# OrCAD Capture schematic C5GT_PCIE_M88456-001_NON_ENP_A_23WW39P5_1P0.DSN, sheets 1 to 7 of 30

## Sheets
1 Title, Note, Block Diagram: title: Cyclone V_GT FPGA DK (Non-ENP); note: M88456-001 (100-0330705-A1)
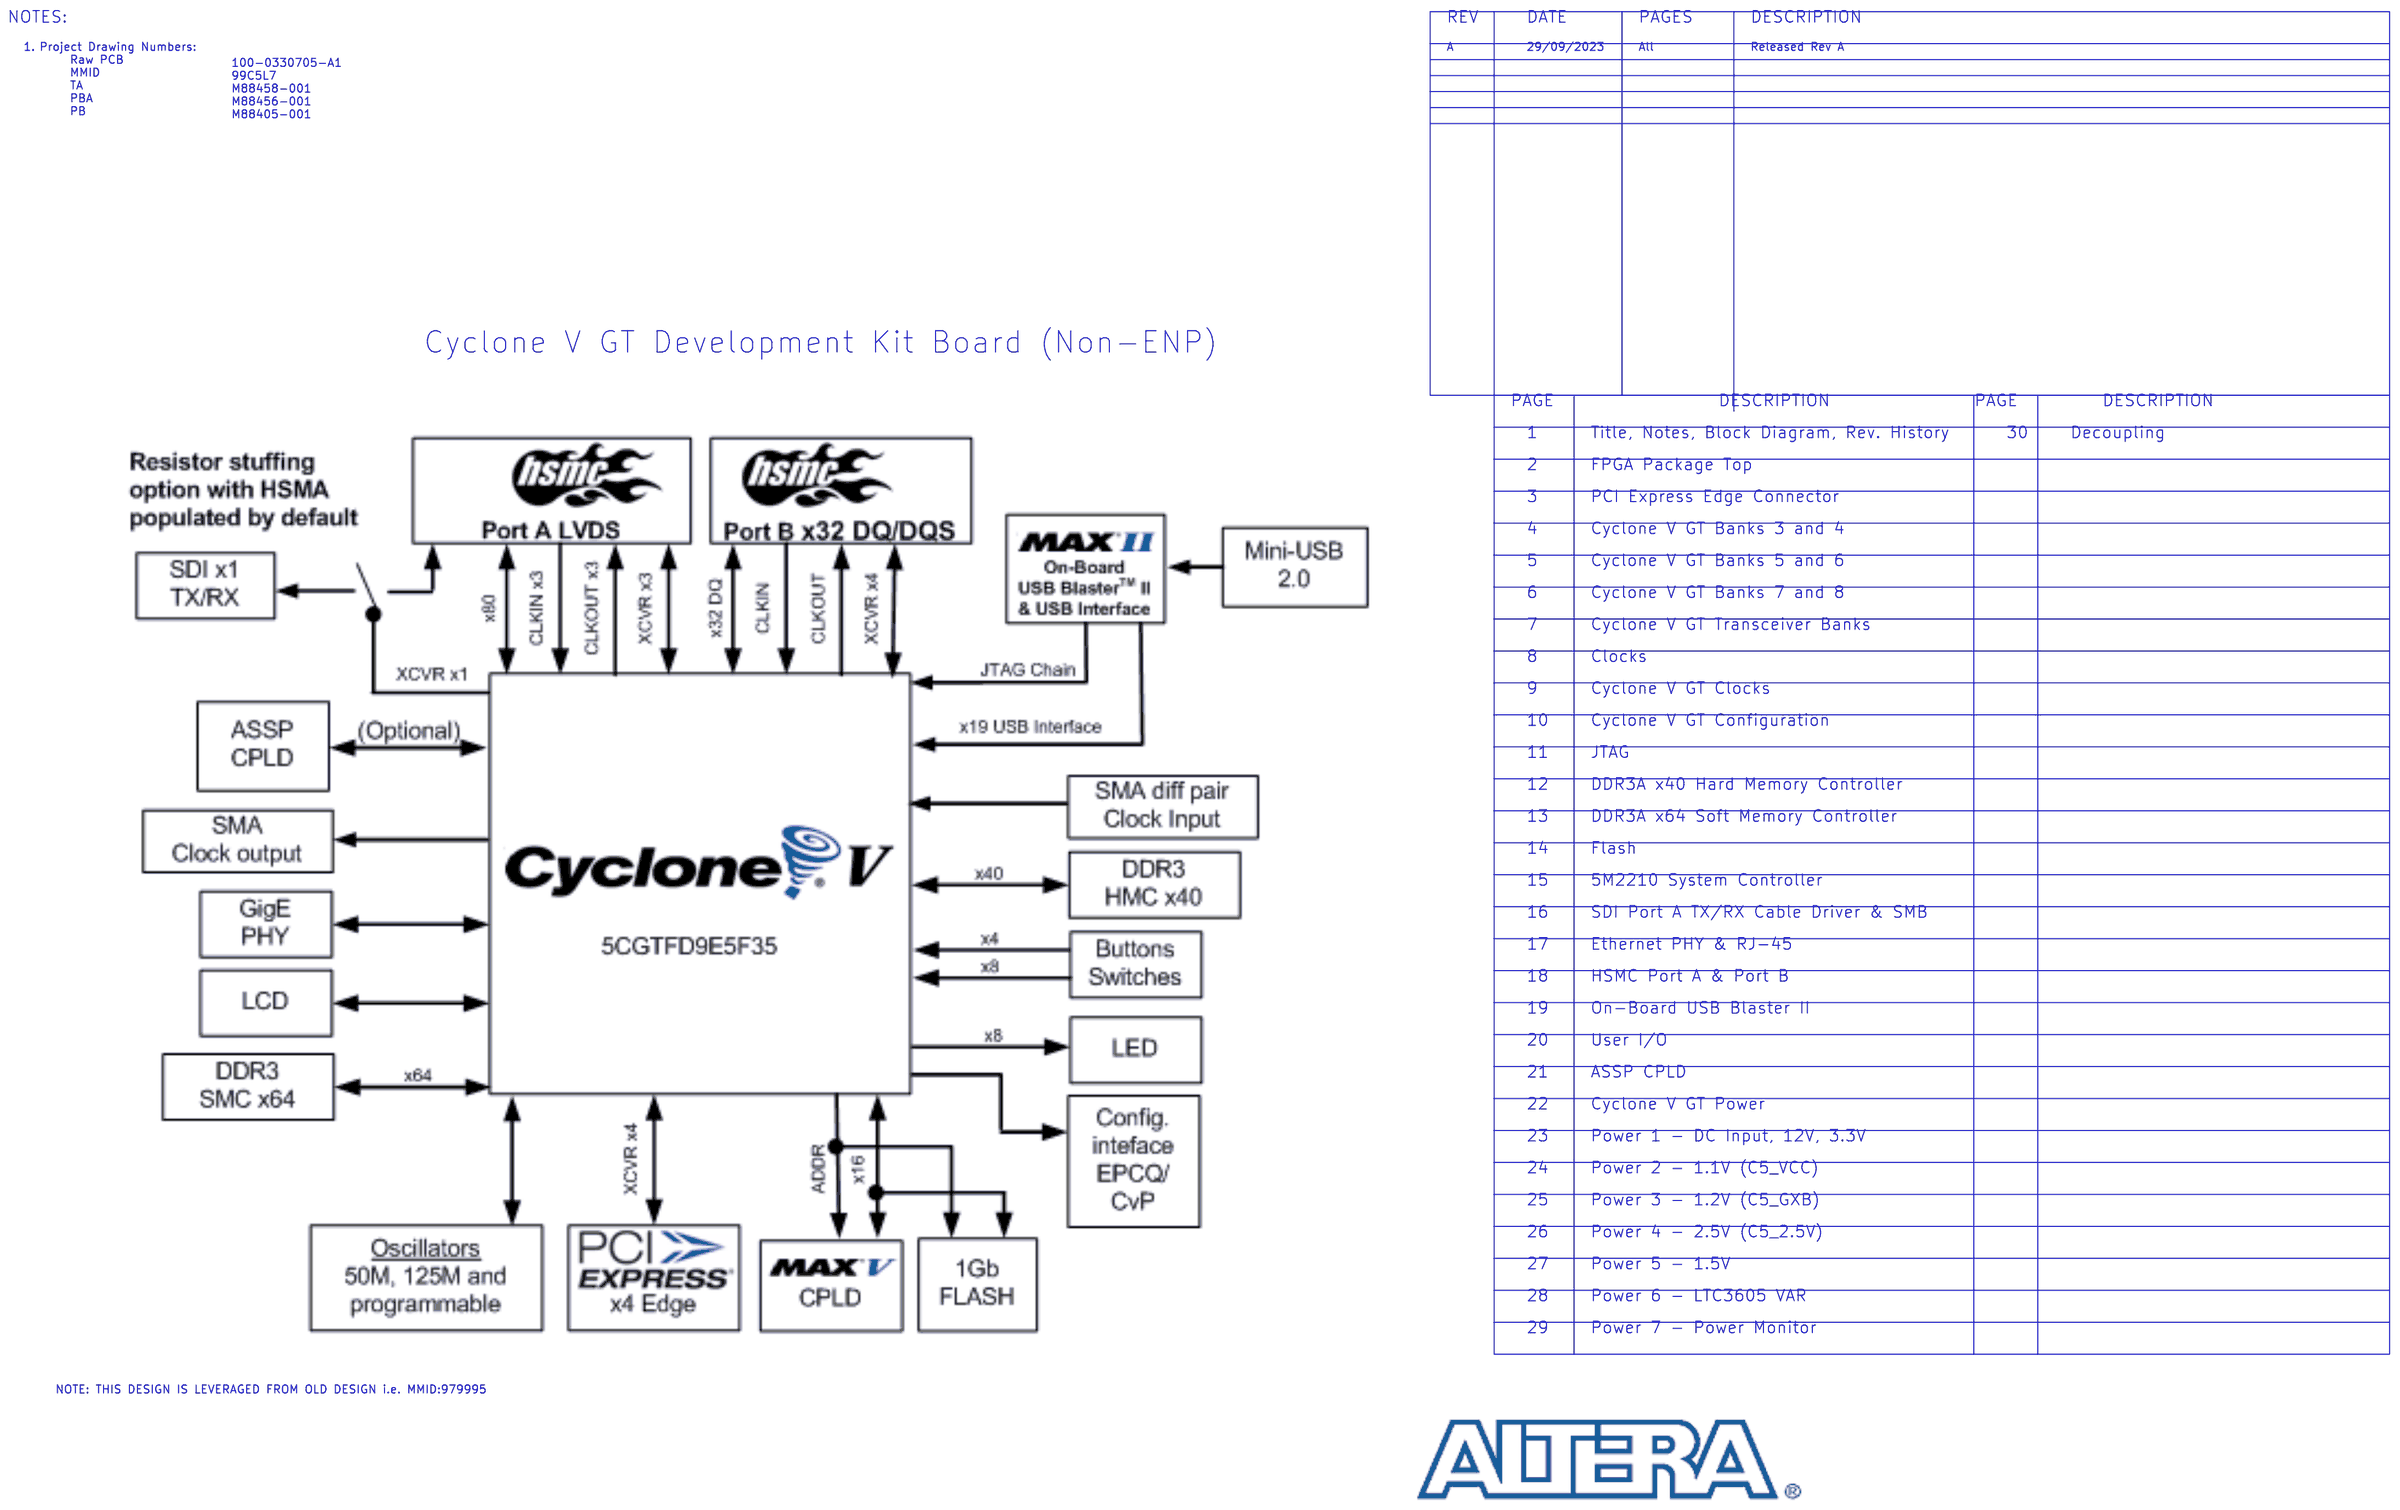
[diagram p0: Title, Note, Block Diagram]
2 Cyclone V, Package Top
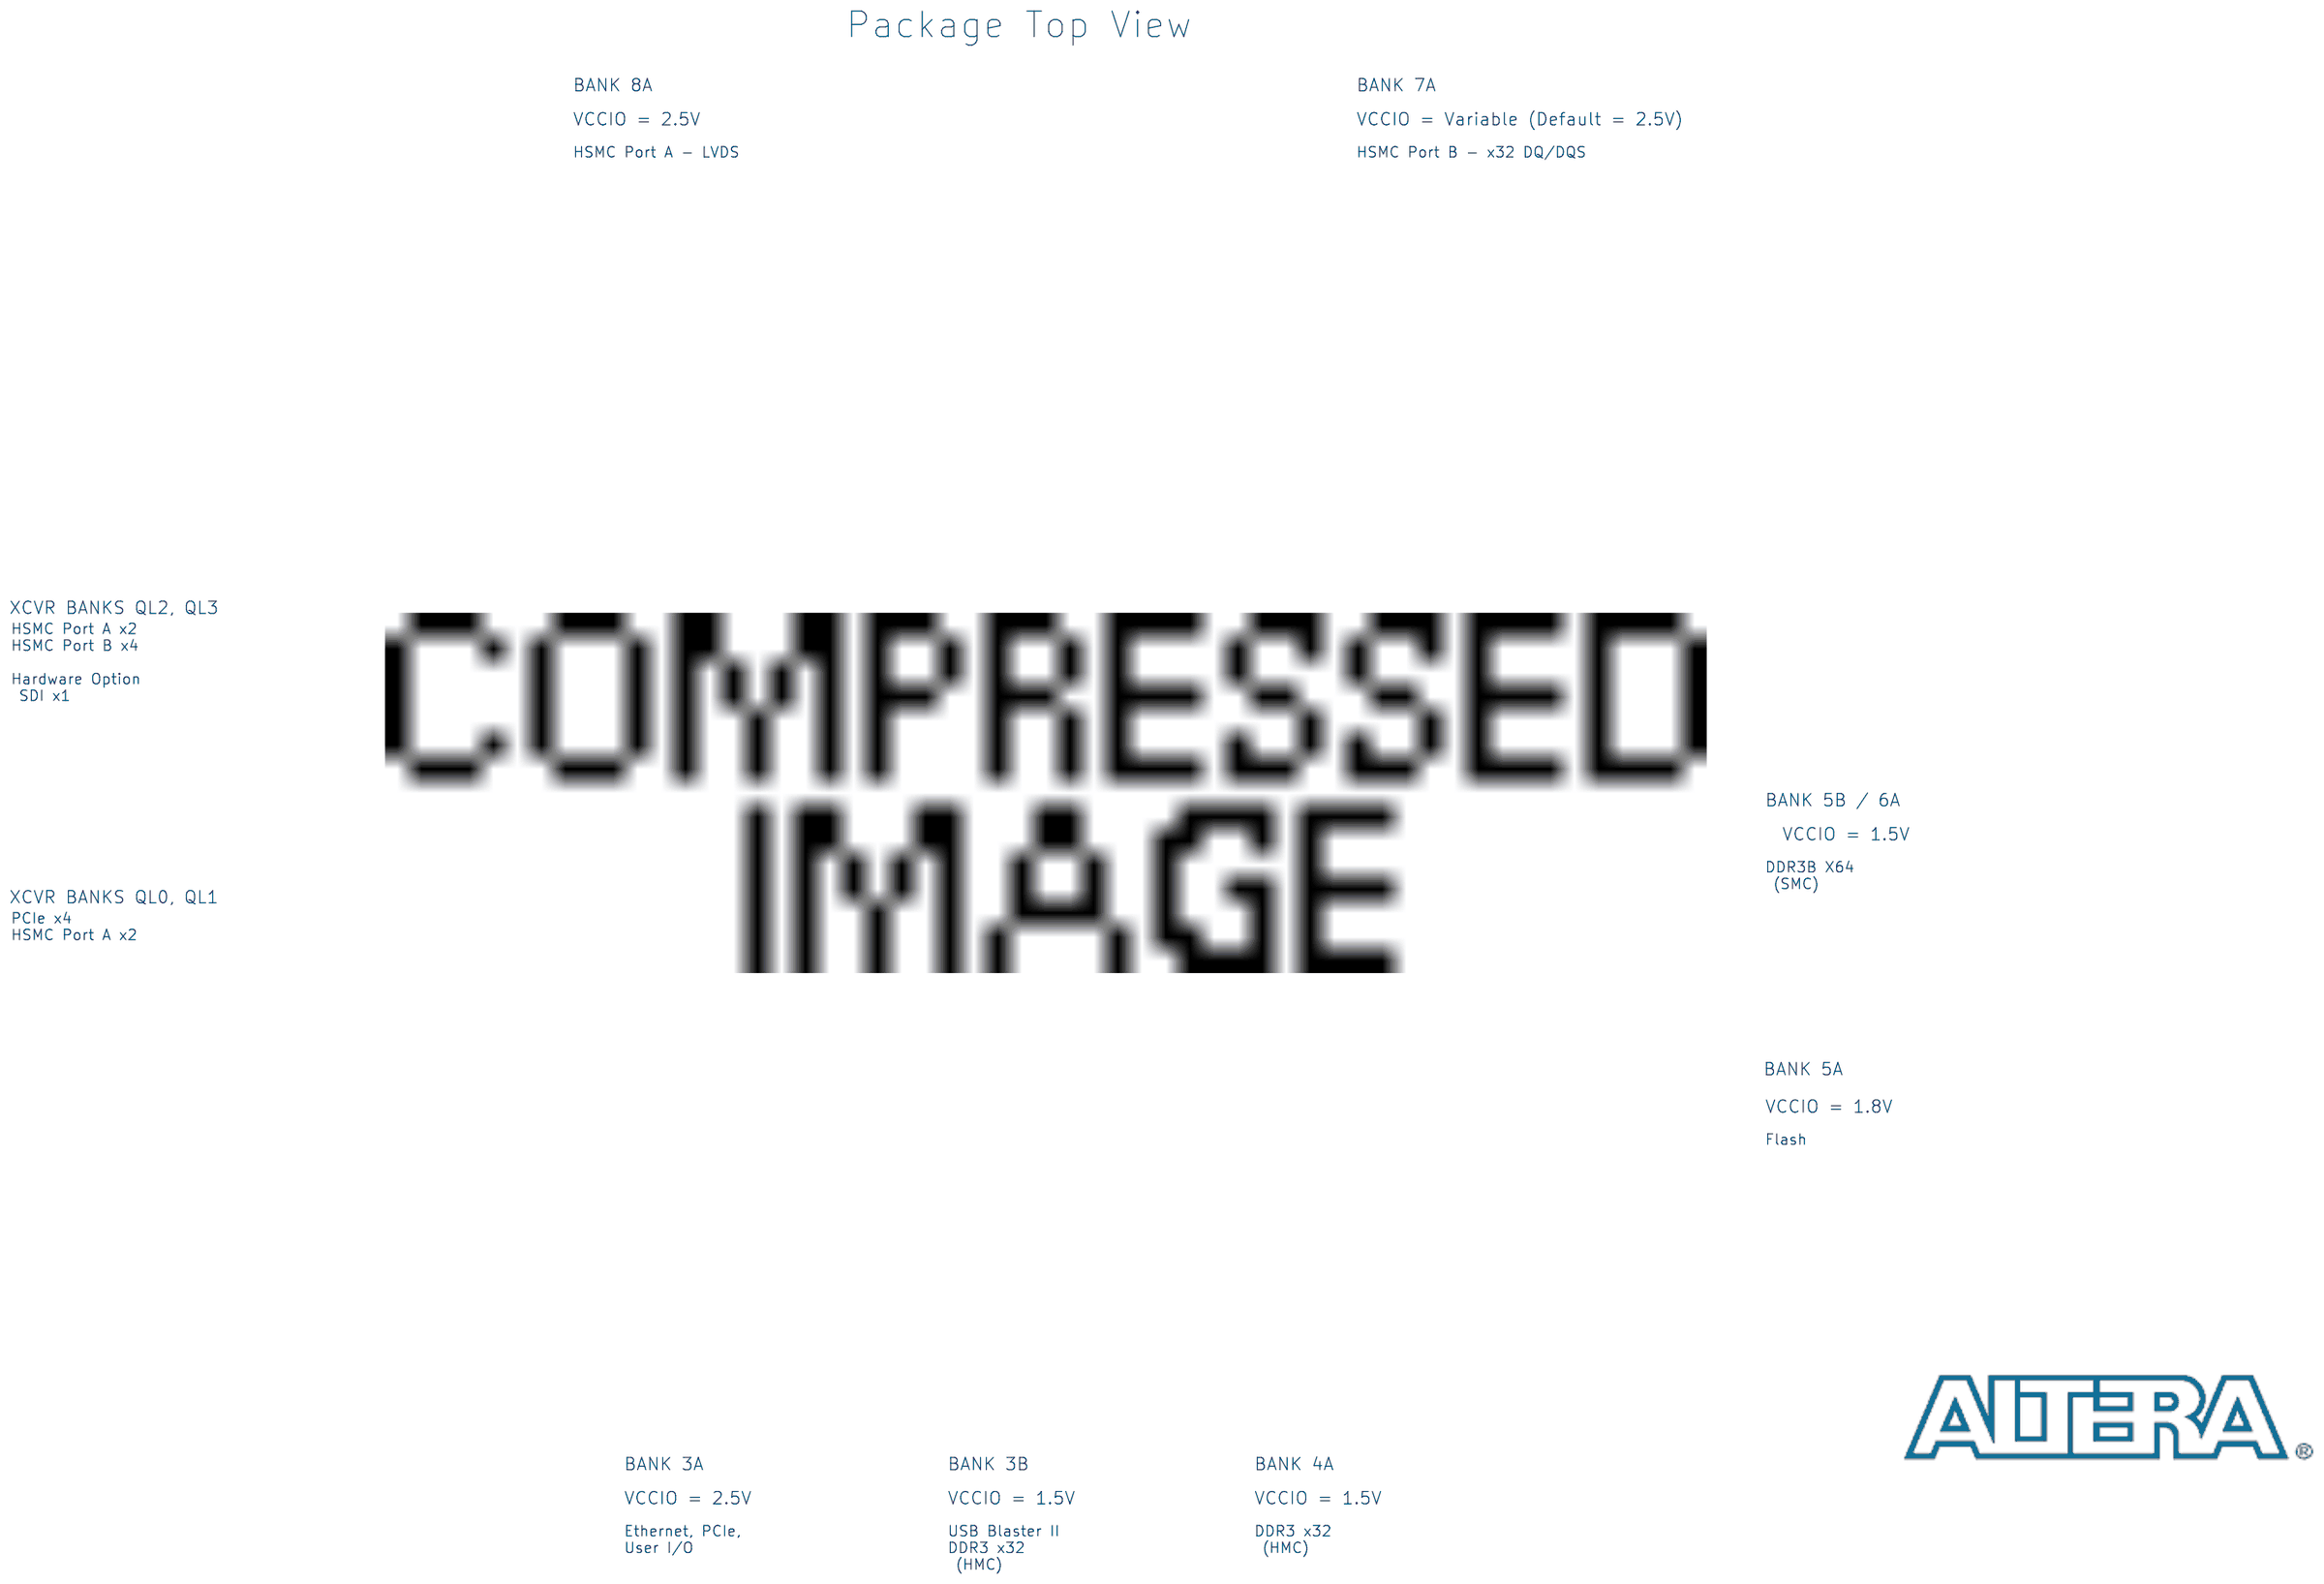
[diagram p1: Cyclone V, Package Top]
3 PCI Express Edge Connector: size B
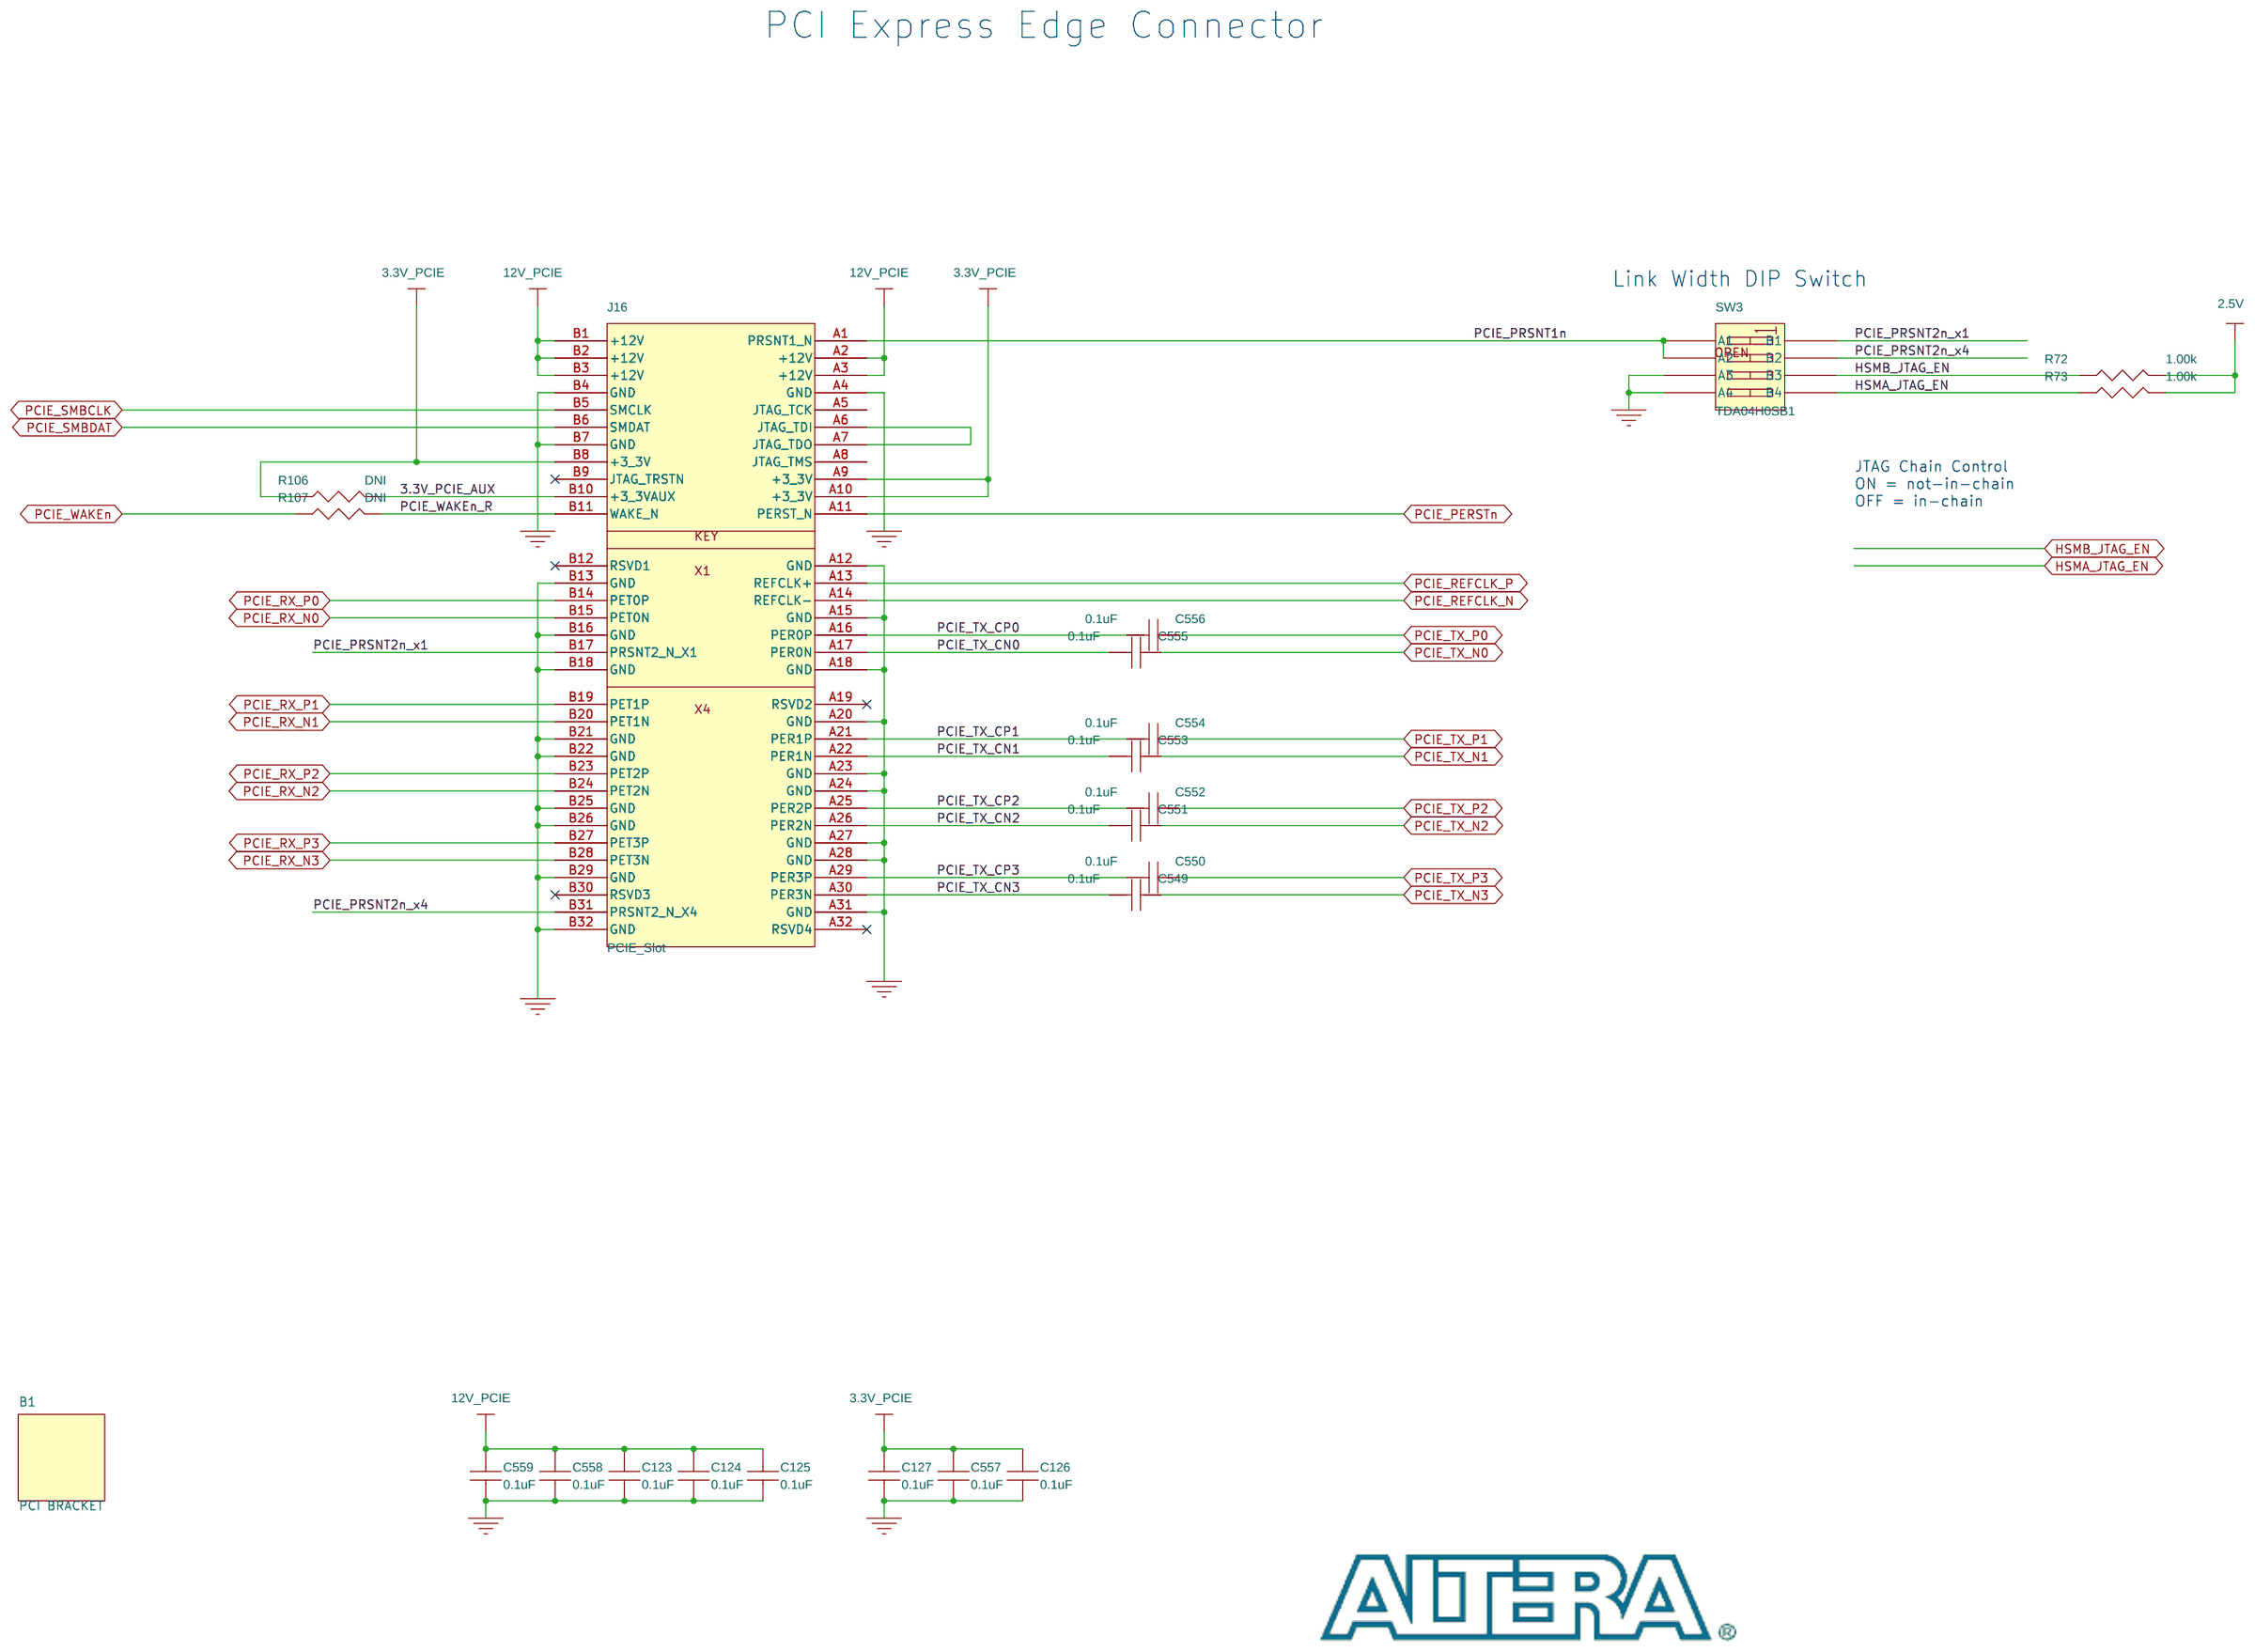
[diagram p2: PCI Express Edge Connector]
4 Cycone V GT, B3 & B4: size B
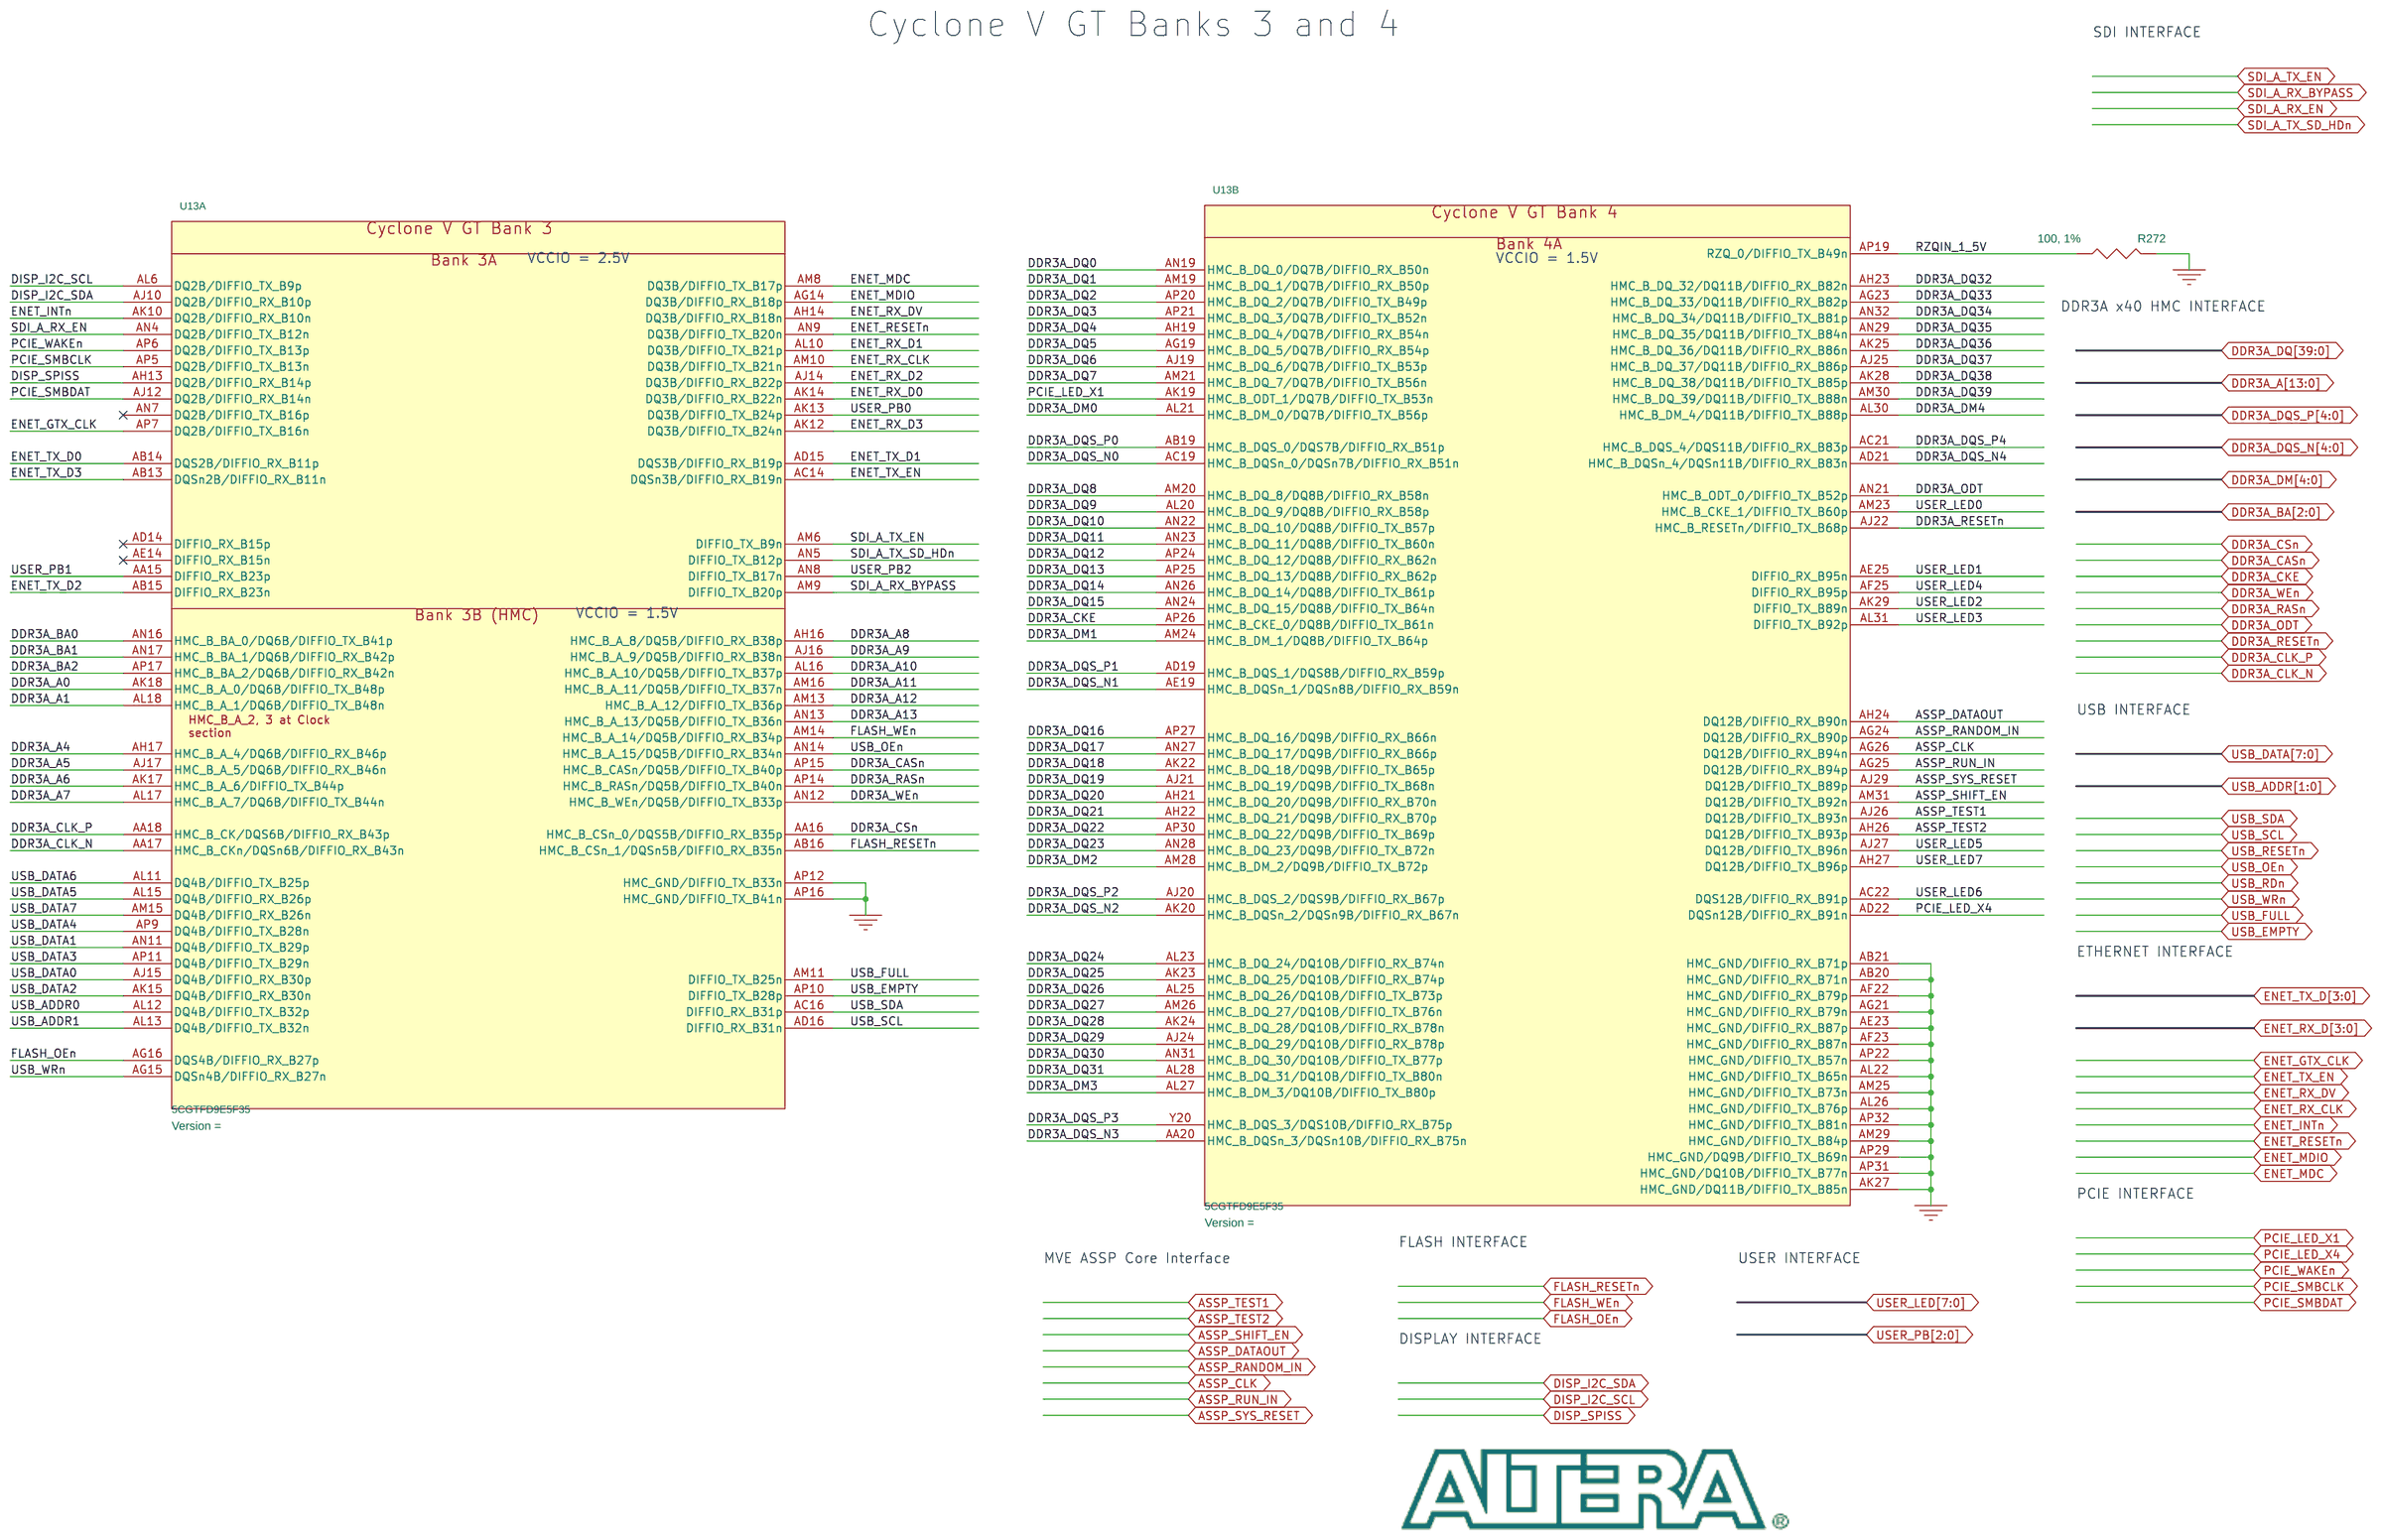
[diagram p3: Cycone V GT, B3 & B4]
5 Cycone V GT, B5 & B6: size B
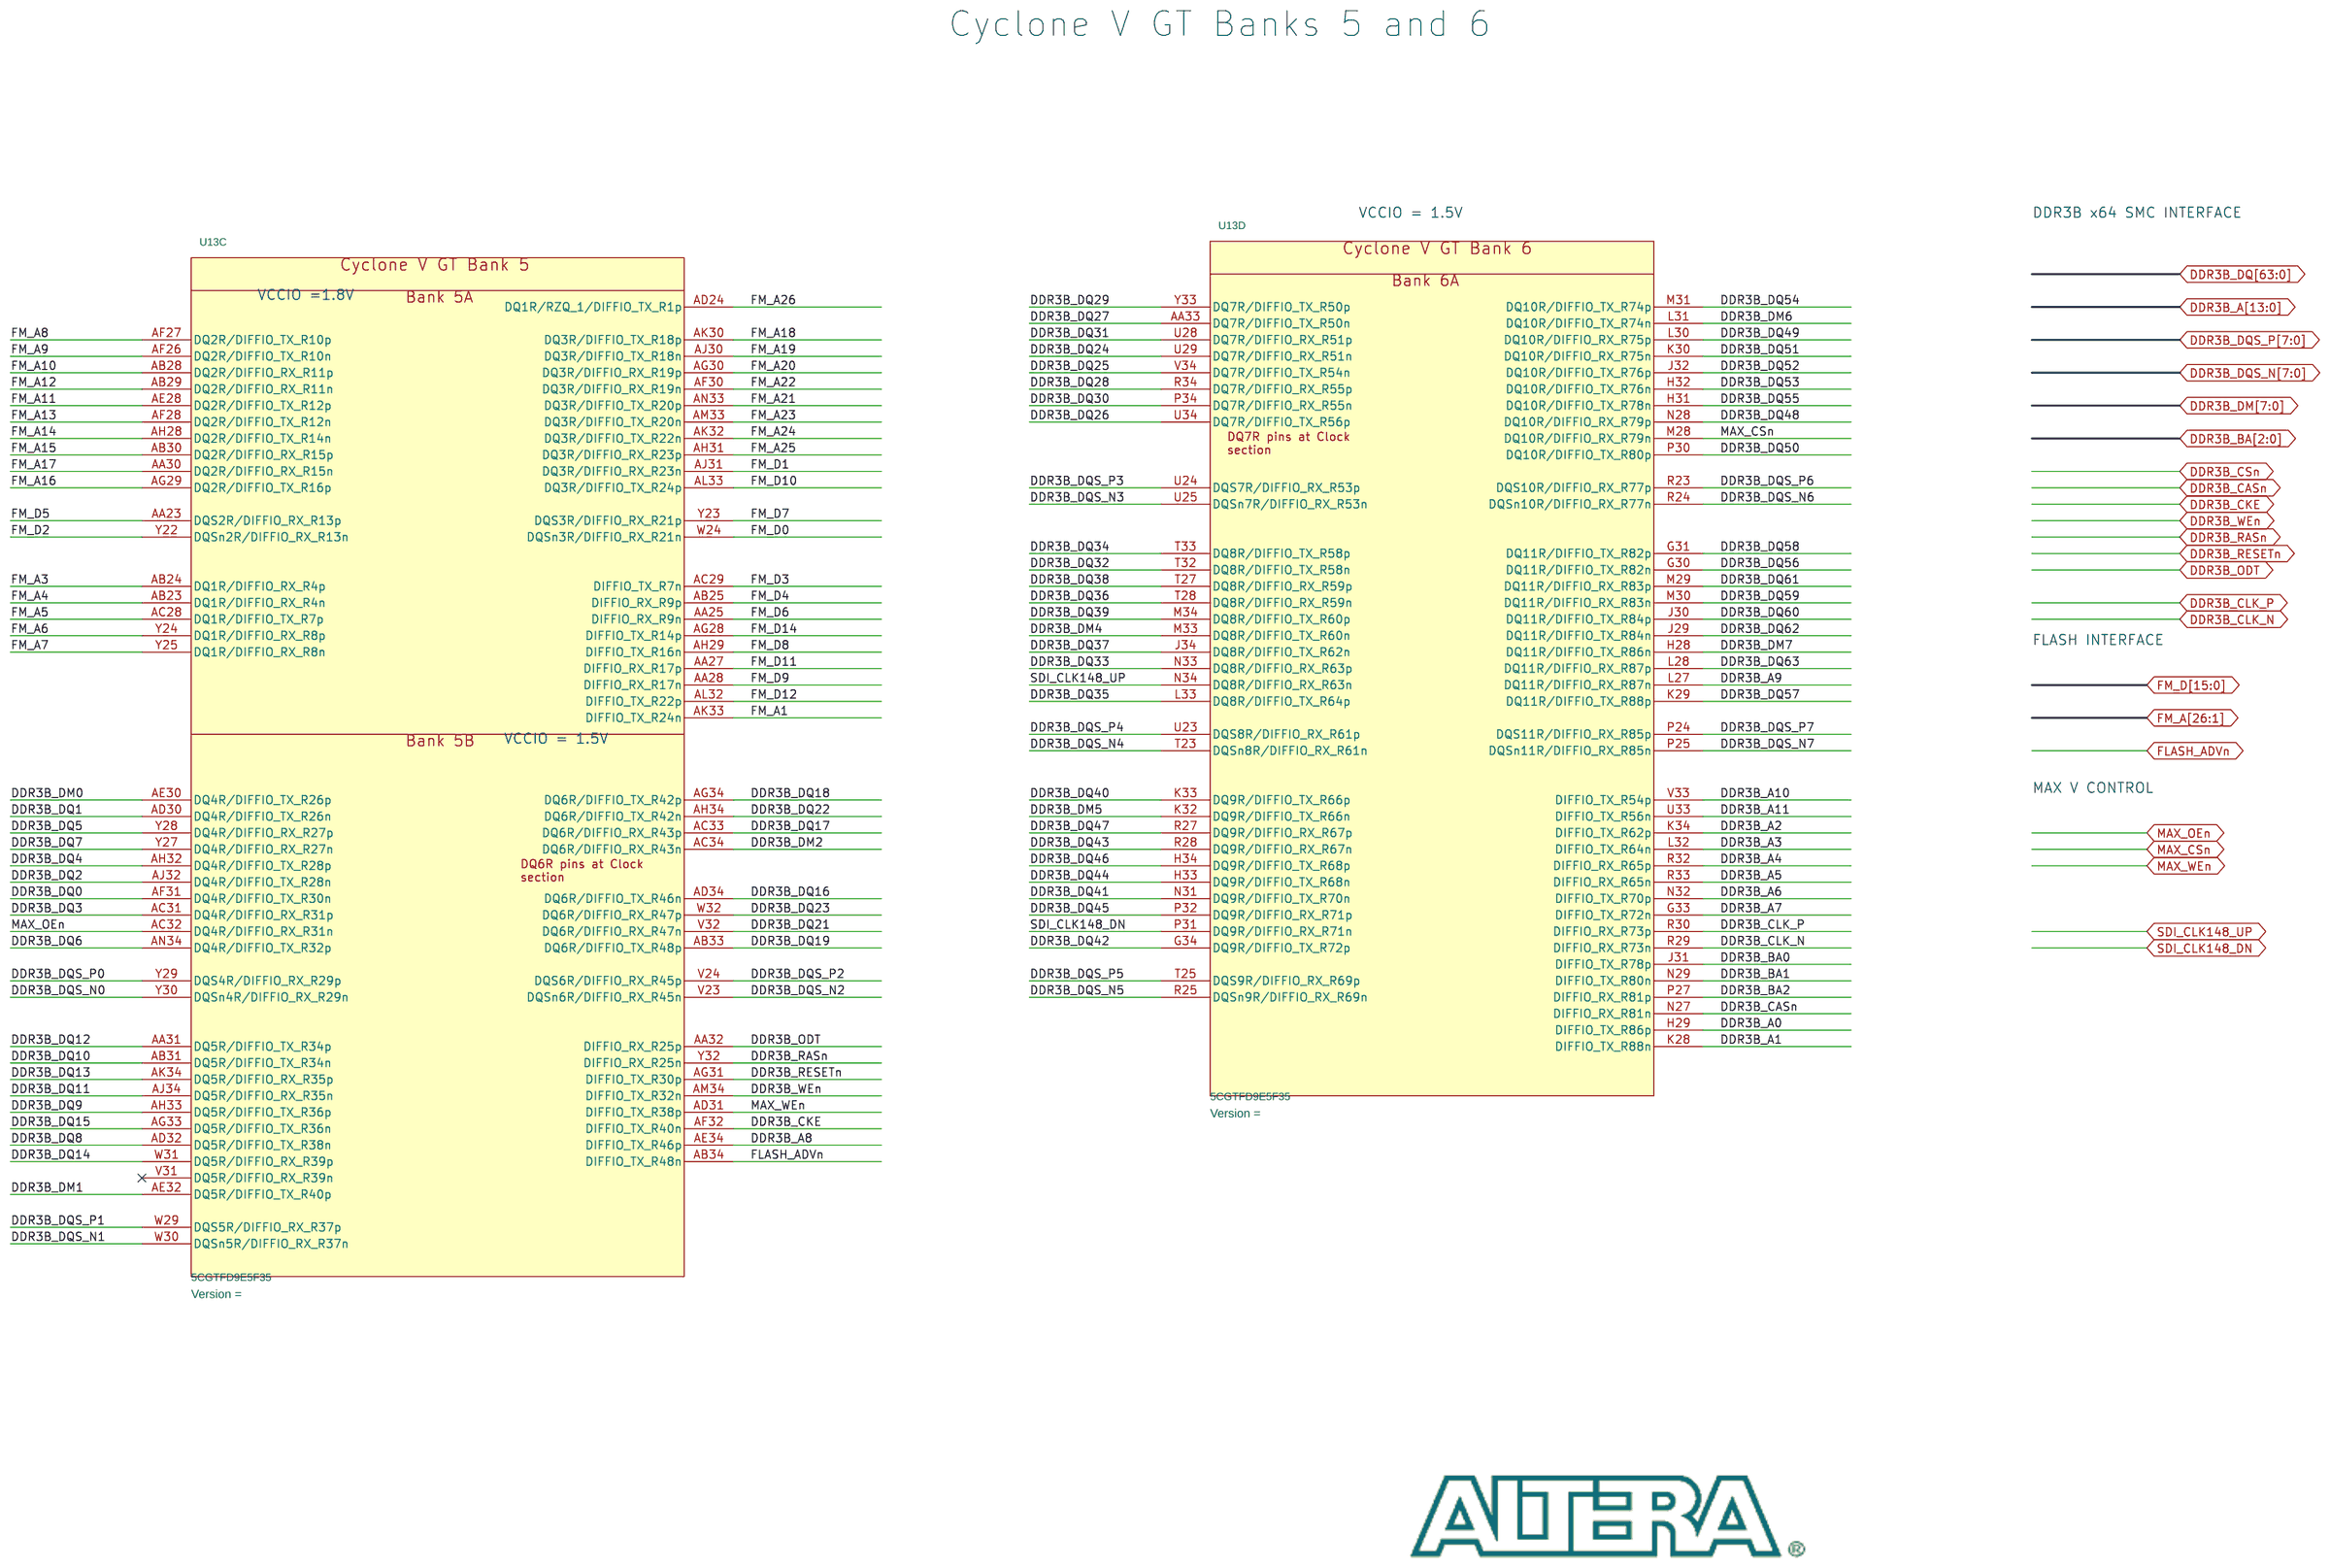
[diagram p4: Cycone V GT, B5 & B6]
6 Cycone V GT, B7 & B8: size B
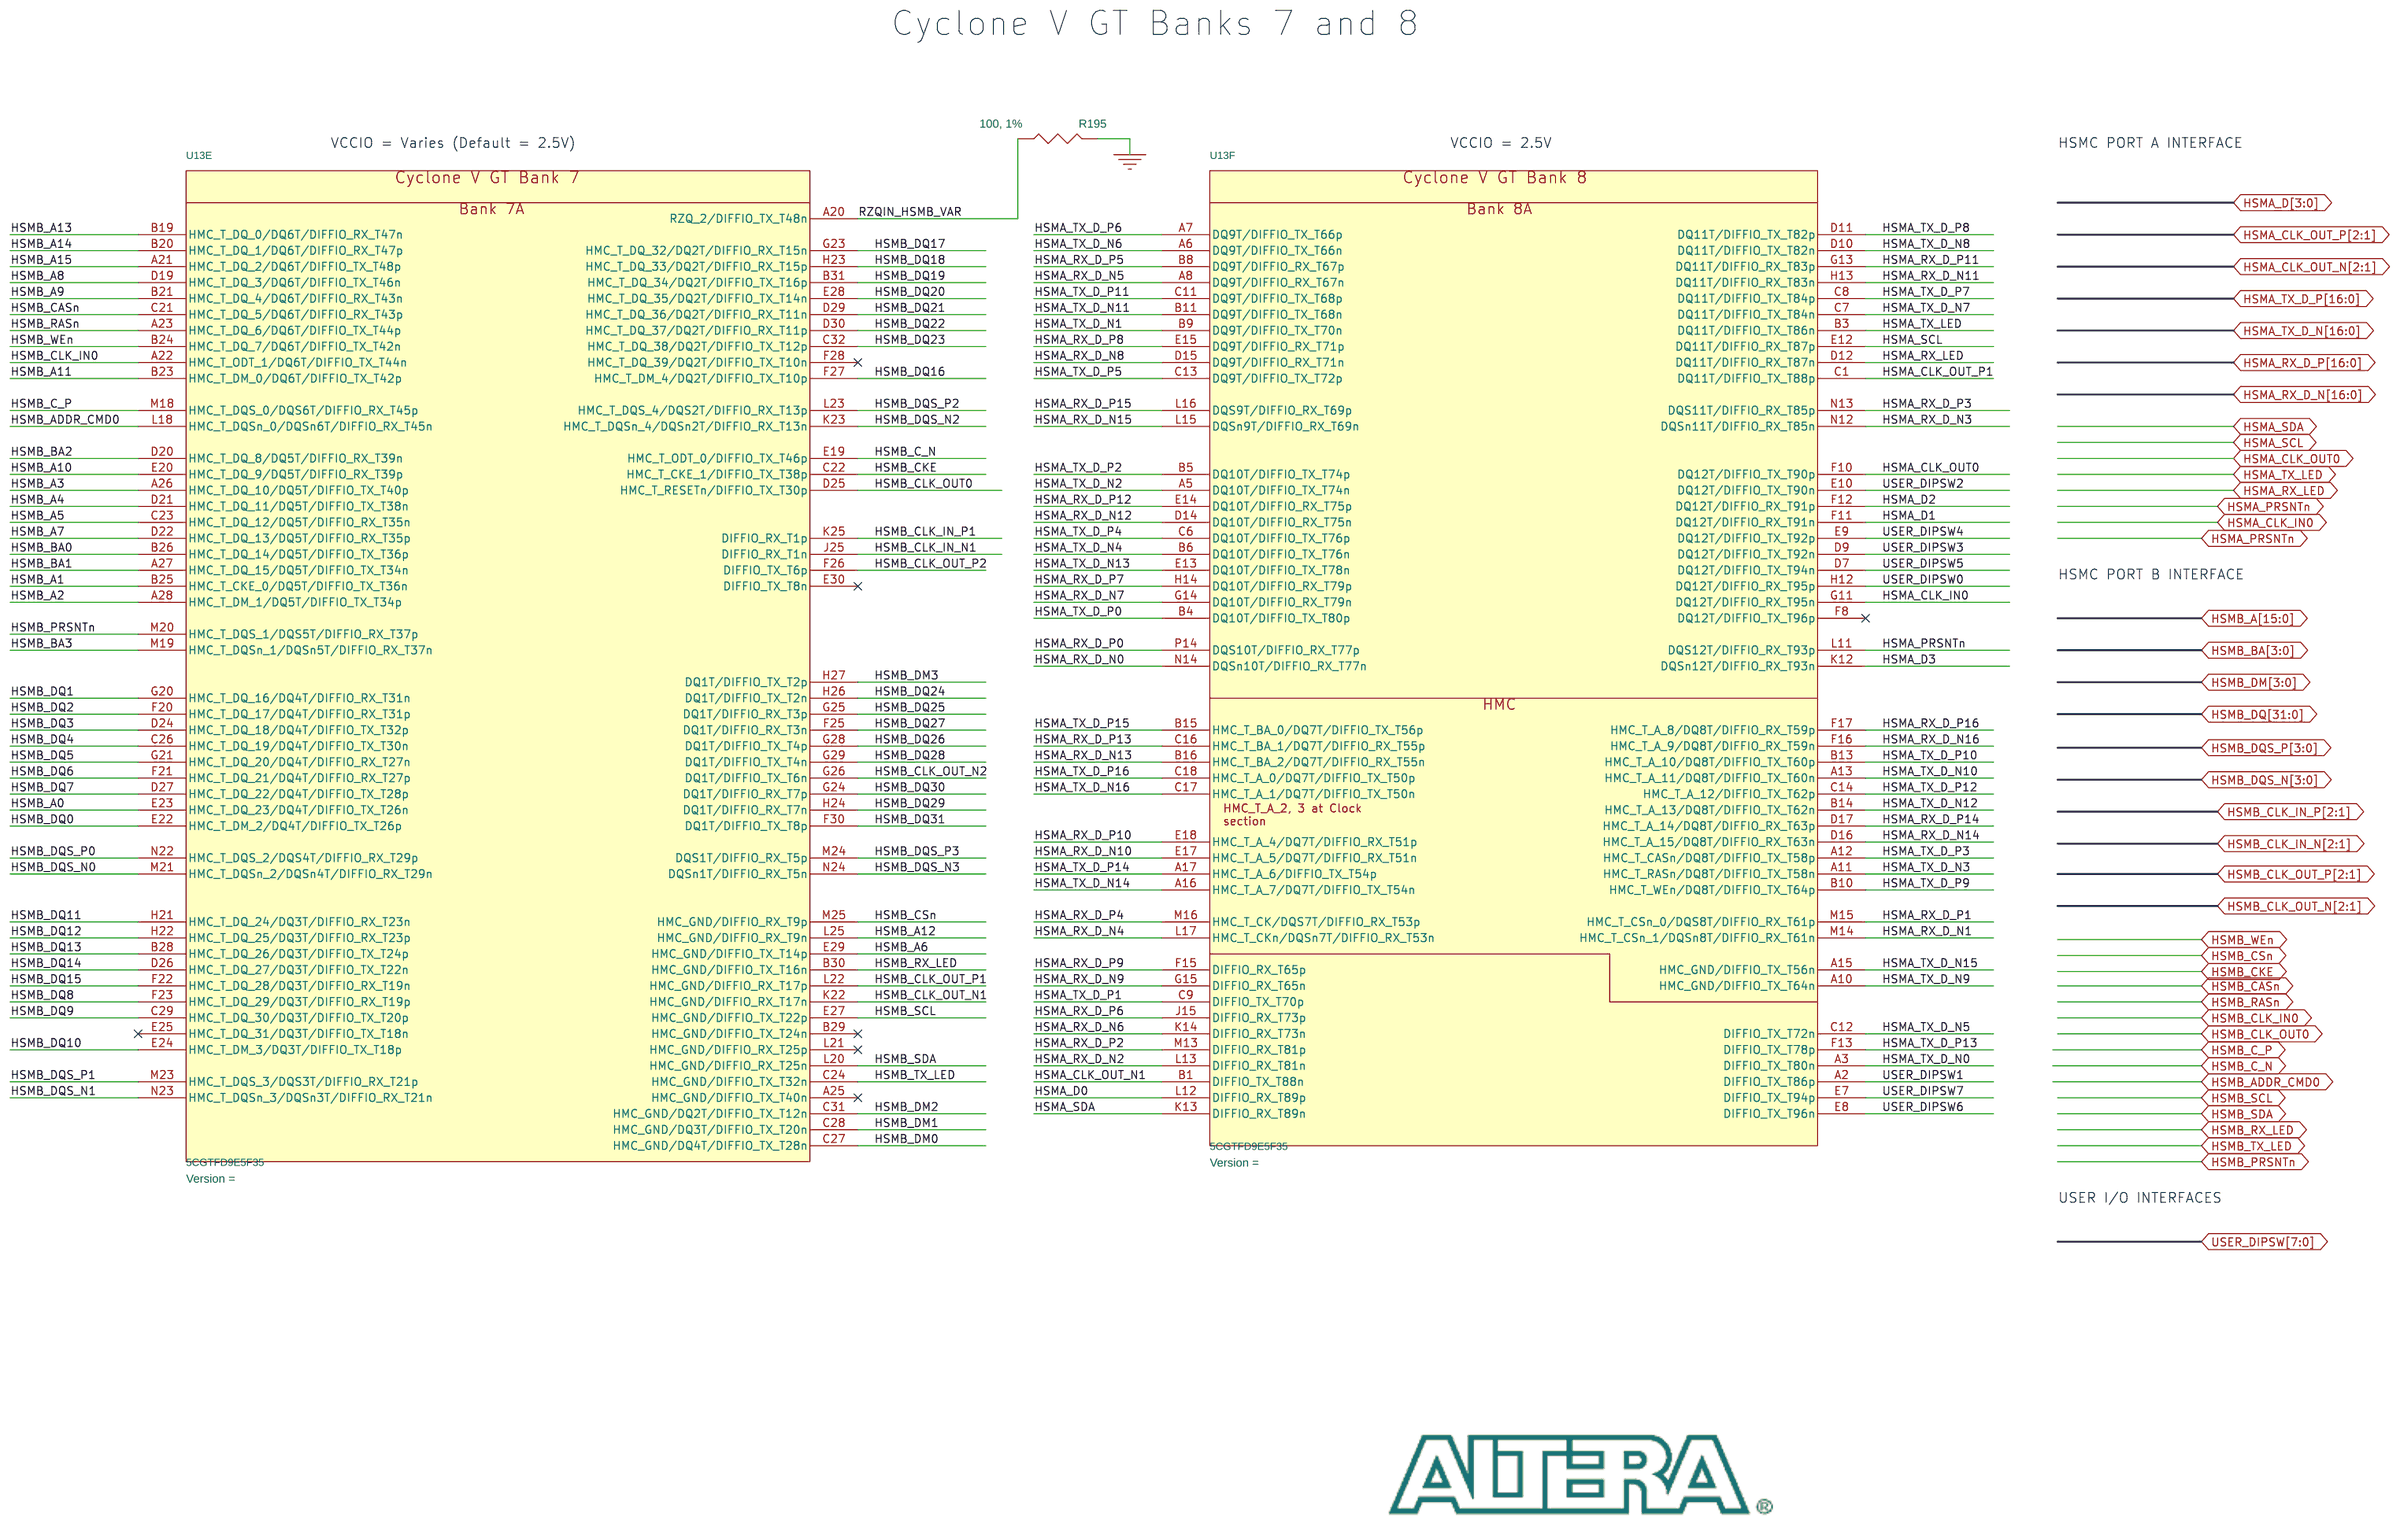
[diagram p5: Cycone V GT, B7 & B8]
7 Cyclone V GT,  XCVRs: size B
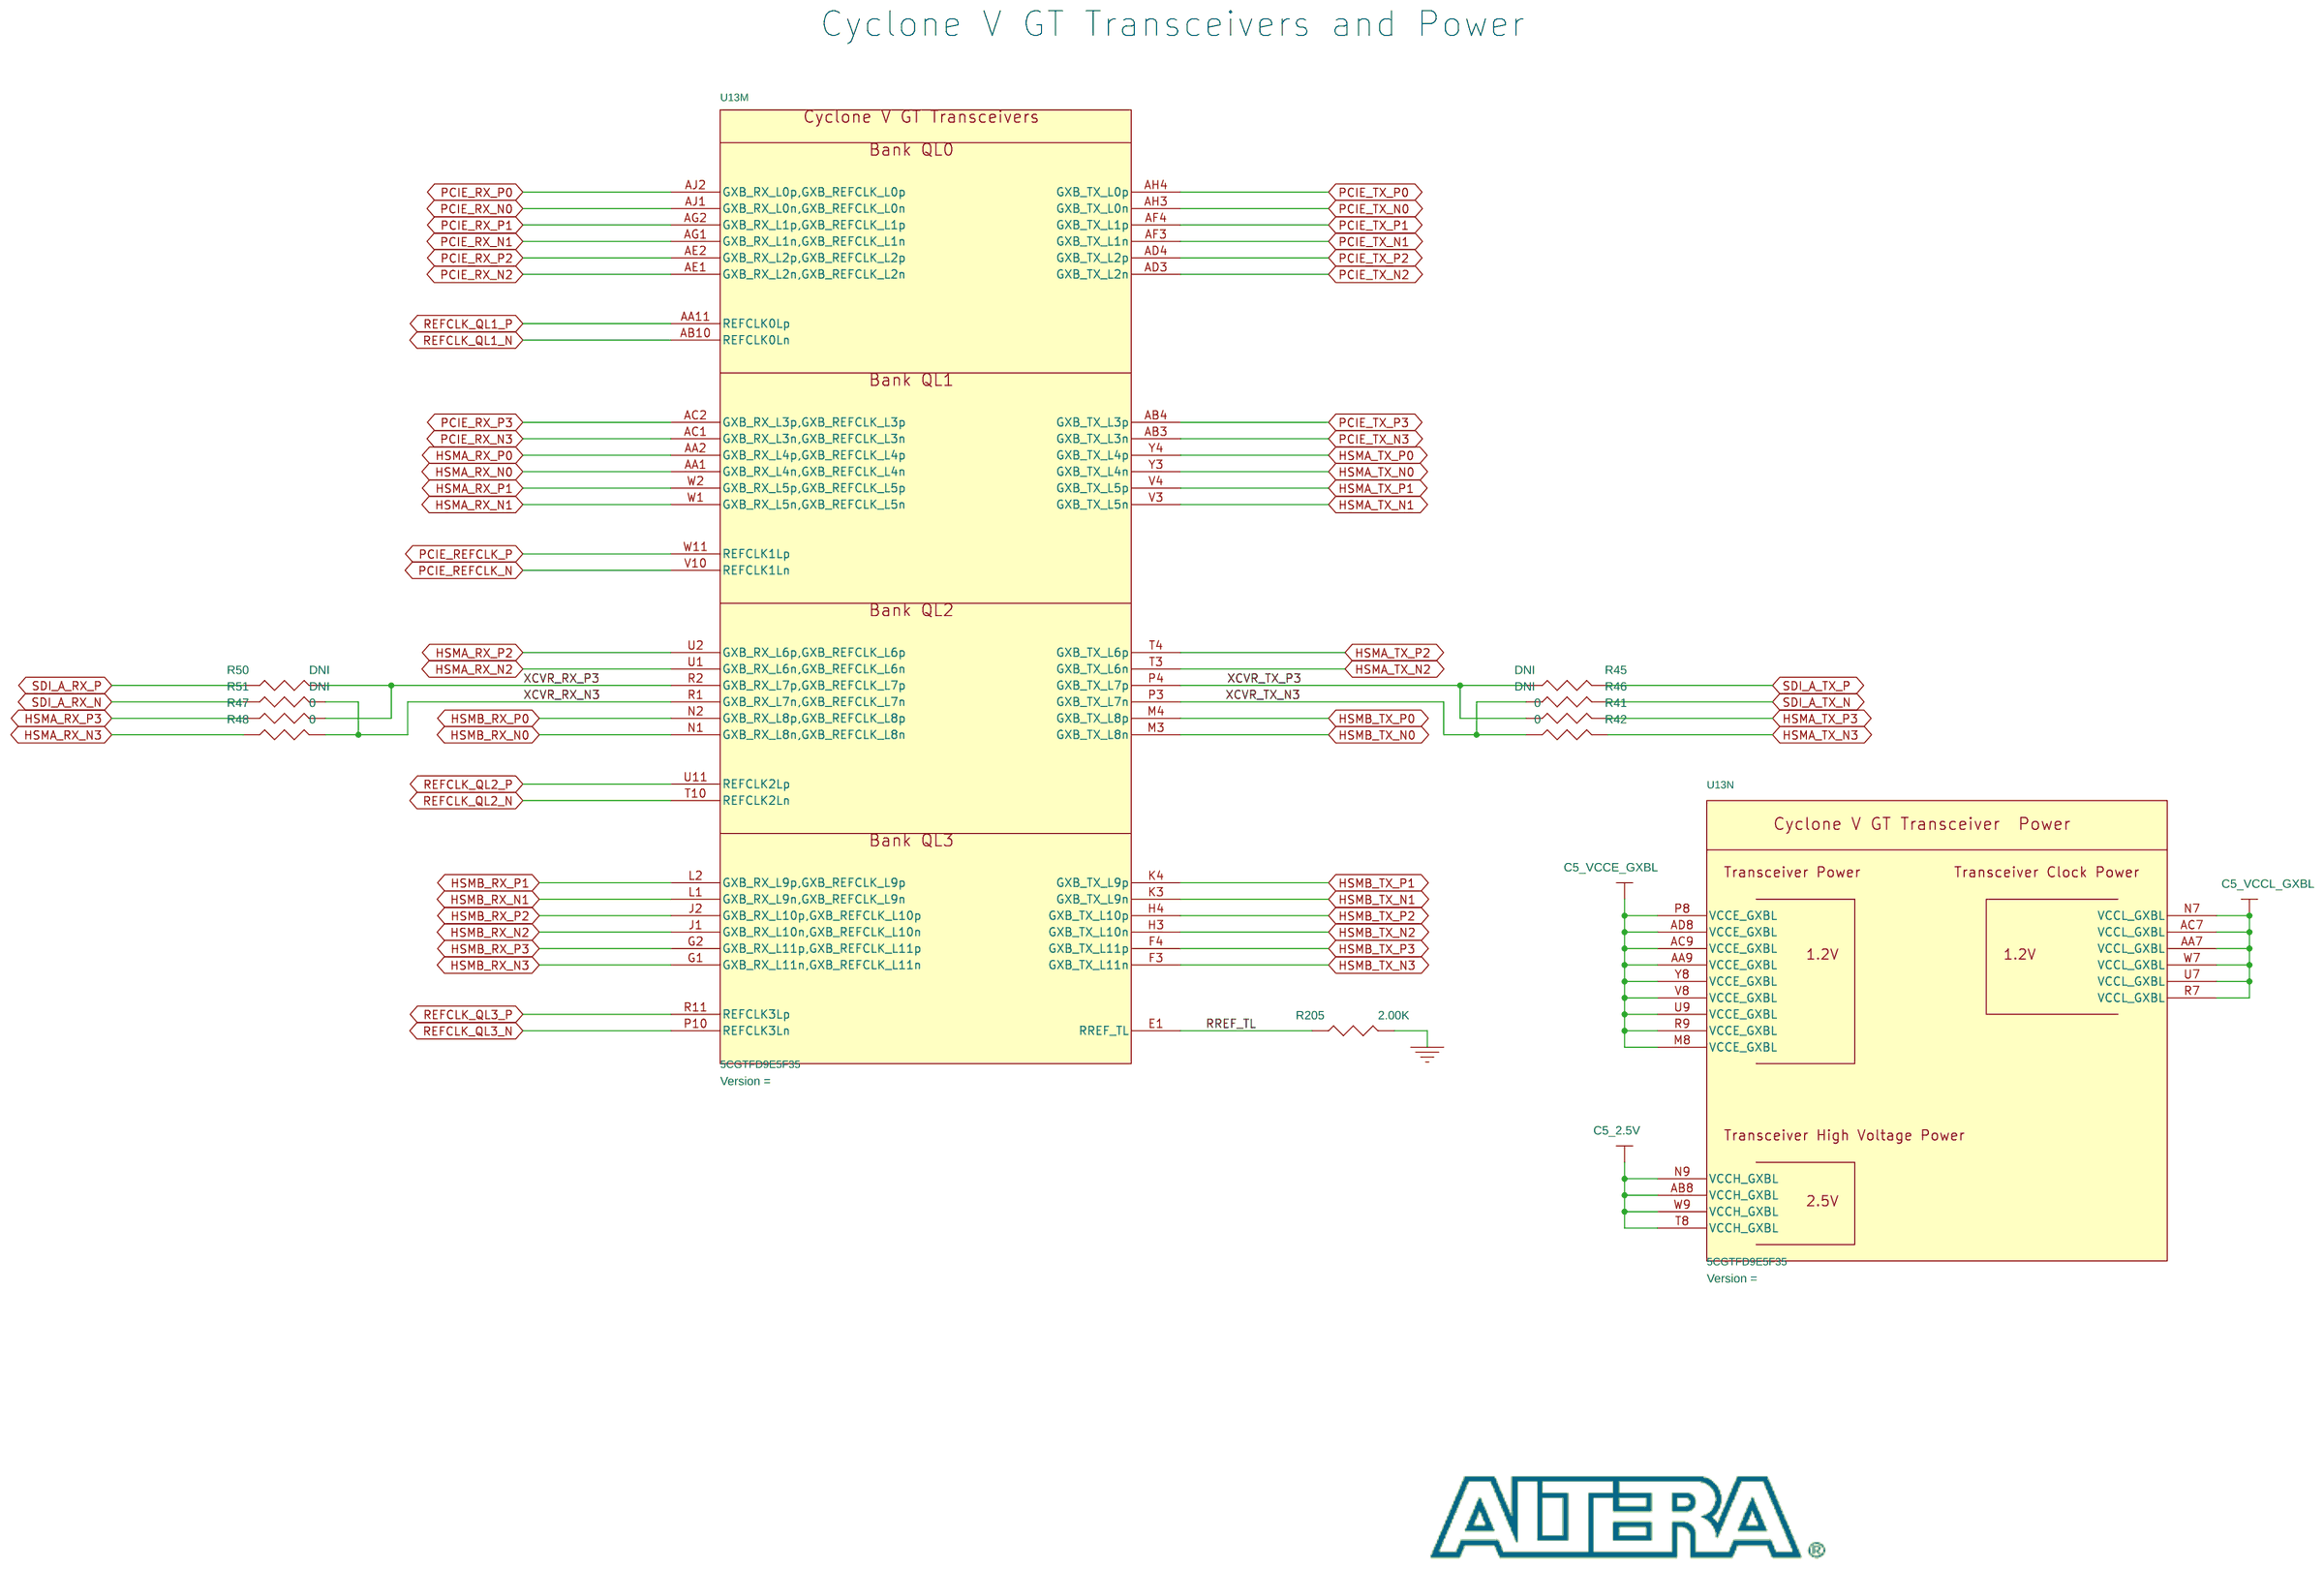
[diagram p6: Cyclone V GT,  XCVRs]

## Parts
sheet Cyclone V GT,  XCVRs
R41  0  [0402]
R42  0  [0402]
R45  DNI  [0402]
R46  DNI  [0402]
R47  0  [0402]
R48  0  [0402]
R50  DNI  [0402]
R51  DNI  [0402]
R205  2.00K  [0402]
U13  5CGTFD9E5F35  [F1152]  (sections A,B,C,D,E,F,G,H,I,J,K,L,M,N,O)
sheet Cycone V GT, B3 & B4
R272  100, 1%  [0402]
sheet Cycone V GT, B7 & B8
R195  100, 1%  [0402]
sheet PCI Express Edge Connector
B1  PCI BRACKET  [NULL]
C123  0.1uF  [0402]
C124  0.1uF  [0402]
C125  0.1uF  [0402]
C126  0.1uF  [0402]
C127  0.1uF  [0402]
C549  0.1uF  [0402]
C550  0.1uF  [0402]
C551  0.1uF  [0402]
C552  0.1uF  [0402]
C553  0.1uF  [0402]
C554  0.1uF  [0402]
C555  0.1uF  [0402]
C556  0.1uF  [0402]
C557  0.1uF  [0402]
C558  0.1uF  [0402]
C559  0.1uF  [0402]
J16  PCIE_Slot  [PCIX-4PORT]
R72  1.00k  [0402]
R73  1.00k  [0402]
R106  DNI  [0402]
R107  DNI  [0402]
SW3  TDA04H0SB1  [DIPSWITCH_SMT_QUAD]

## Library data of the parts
R41 R42 R45-R48 R50 R51 = RES_0_OHM_5%_1_16W_0402_SMD: IPN: A93549-001
R205 = RESISTOR: RES,2.00K OHMS,1.0%,1/16W,0402; IPN: A93548-138; Item Num: P02-11376R; Lead Free Status: No; Manufacturer: Panasonic; Manufacturer Part Num: ERJ-2RKF2001X; Manufacturer's Part No.: ERJ-2RKF2001X; Num Pins: 2; Part Class: RESISTORS; Price: 0; RoHS Compliant: Yes
U13 = 5CGTFD9E5F35: IC - FPGA, Cyclone V GT F1152, 301K LEs, (35x35)mm BGA, leadfree; Created by: pmurray; Date: 10/29/12; IPN: 965959; Item Num: P01-17810R; Manufacturer: Altera; Manufacturer Part Num: 5CGTFD9E5F35C7N
R195 R272 = RESISTOR: RES,100 OHMS,1.0%,1/16W,0402; IPN: A36092-043; Item Num: P02-11381R; Lead Free Status: No; Manufacturer: Panasonic; Manufacturer Part Num: ERJ-2RKF1000X; Num Pins: 2; Part Class: Resistors; Price: 0; RoHS Compliant: Yes; Tolerance: 1%
B1 = BLANK_PART: CUSTOM PCI BRACKET Cyclone V GT DEV KIT BOARD CUTOUTS FOR RJ45, mini-USB, 2X SMB; IPN: K14360-001; Item Num: P12-26848R; Manufacturer: Gompf Brackets, Inc.; Manufacturer Part Num: 9456-0357LC
C123-C127 C549-C559 = CAP: CAP - CERAMIC,  0.1UF 0402 25VDC Y5V; AGILE_LINK: http://sj-agile9app/Agile/PLMServlet?action=OpenEmailObject&classid=10000&objid=213459527; IPN: K13560-001; Item Num: P03-15057R; LIFECYCLE_PHASE: Active; Lead Free Status: Lead Free; MFR_LIFECYCLE: Active; Manufacturer: Murata; Manufacturer Part Num: GRM155F51E104ZA01D; Num Pins: 2; PART_SUBCLASS: CAPACITORS; Part Class: CAPACITORS; RATED_VOLTAGE: 25V; RoHS Compliant: RoHS Compliant; TOLERANCE: +80%/-20%
J16 = PCIE_Bracket_X4: IPN: #N/A; Item Num: NA; Manufacturer: NA; Manufacturer's Part No.: NA
R72 R73 = RESISTOR: RES,1.00K OHMS,1.0%,1/16W,0402; IPN: G60609-021; Item Num: P02-11372R; Lead Free Status: No; Manufacturer: Panasonic; Manufacturer Part Num: ERJ-2RKF1001X; Num Pins: 2; Part Class: Resistors
R106 R107 = RESISTOR: RES ZERO OHM 1/16W 5% 0402 SMD; IPN: A93549-001; Item Num: P02-14020R; Lead Free Status: No; Manufacturer: Panasonic; Manufacturer Part Num: ERJ-2GE0R00X; Manufacturer's Part No.: ERJ-2GE0R00X; Num Pins: 2; Part Class: RESISTORS; Price: 0; RoHS Compliant: Yes
SW3 = SPST4: SWITCHES - 4 POS, 8 PIN, Ultra-mini SMT Half-pitch Slider DIP Switch; AGILE_LINK: http://sj-agile9app/Agile/PLMServlet?action=OpenEmailObject&classid=10000&objid=258073635; IPN: A35353-010; Item Num: P11-24098R; LIFECYCLE_PHASE: Preliminary; Lead Free Status: Not Lead Free; MFR_LIFECYCLE: Active; Manufacturer: C & K Components/ITT Industries; Num Pins: 8; PART_SUBCLASS: SWITCHES; RoHS Compliant: RoHS Compliant

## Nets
2.5V: R72.2 R73.2 ; also on sheet 8 10 11 15 17 19 20 22 26 29
3.3V_PCIE: C126.2 C127.2 C557.2 J16.A9(+3_3V) J16.A10(+3_3V) J16.B8(+3_3V) R106.1 ; also on sheet 23
3.3V_PCIE_AUX: J16.B10(+3_3VAUX) R106.2
12V_PCIE: C123.2 C124.2 C125.2 C558.2 C559.2 J16.A2(+12V) J16.A3(+12V) J16.B1(+12V) J16.B2(+12V) J16.B3(+12V) ; also on sheet 23
GND: C123.1 C124.1 C125.1 C126.1 C127.1 C557.1 C558.1 C559.1 J16.A4(GND) J16.A12(GND) J16.A15(GND) J16.A18(GND) J16.A20(GND) J16.A23(GND) J16.A24(GND) J16.A27(GND) J16.A28(GND) J16.A31(GND) J16.B4(GND) J16.B7(GND) J16.B13(GND) J16.B16(GND) J16.B18(GND) J16.B21(GND) J16.B22(GND) J16.B25(GND) J16.B26(GND) J16.B29(GND) J16.B32(GND) R195.1 R205.2 R272.1 SW3.3(A3) SW3.4(A4) U13.AB20(HMC_GND/DIFFIO_RX_B71n) U13.AB21(HMC_GND/DIFFIO_RX_B71p) U13.AE23(HMC_GND/DIFFIO_RX_B87p) U13.AF22(HMC_GND/DIFFIO_RX_B79p) U13.AF23(HMC_GND/DIFFIO_RX_B87n) U13.AG21(HMC_GND/DIFFIO_RX_B79n) U13.AK27(HMC_GND/DQ11B/DIFFIO_TX_B85n) U13.AL22(HMC_GND/DIFFIO_TX_B65n) U13.AL26(HMC_GND/DIFFIO_TX_B76p) U13.AM25(HMC_GND/DIFFIO_TX_B73n) U13.AM29(HMC_GND/DIFFIO_TX_B84p) U13.AP12(HMC_GND/DIFFIO_TX_B33n) U13.AP16(HMC_GND/DIFFIO_TX_B41n) U13.AP22(HMC_GND/DIFFIO_TX_B57n) U13.AP29(HMC_GND/DQ9B/DIFFIO_TX_B69n) U13.AP31(HMC_GND/DQ10B/DIFFIO_TX_B77n) U13.AP32(HMC_GND/DIFFIO_TX_B81n) ; also on sheet 8 9 10 11 12 13 14 15 16 17 18 19 20 21 22 23 24 25 26 27 28 29 30
ASSP_CLK: U13.AG26(DQ12B/DIFFIO_RX_B94n) ; also on sheet 21
ASSP_DATAOUT: U13.AH24(DQ12B/DIFFIO_RX_B90n) ; also on sheet 21
ASSP_RANDOM_IN: U13.AG24(DQ12B/DIFFIO_RX_B90p) ; also on sheet 21
ASSP_RUN_IN: U13.AG25(DQ12B/DIFFIO_RX_B94p) ; also on sheet 21
ASSP_SHIFT_EN: U13.AM31(DQ12B/DIFFIO_TX_B92n) ; also on sheet 21
ASSP_SYS_RESET: U13.AJ29(DQ12B/DIFFIO_TX_B89p) ; also on sheet 21
ASSP_TEST1: U13.AJ26(DQ12B/DIFFIO_TX_B93n) ; also on sheet 21
ASSP_TEST2: U13.AH26(DQ12B/DIFFIO_TX_B93p) ; also on sheet 21
C5_2.5V: U13.AB8(VCCH_GXBL) U13.N9(VCCH_GXBL) U13.T8(VCCH_GXBL) U13.W9(VCCH_GXBL) ; also on sheet 22 26 30
C5_VCCE_GXBL: U13.AA9(VCCE_GXBL) U13.AC9(VCCE_GXBL) U13.AD8(VCCE_GXBL) U13.M8(VCCE_GXBL) U13.P8(VCCE_GXBL) U13.R9(VCCE_GXBL) U13.U9(VCCE_GXBL) U13.V8(VCCE_GXBL) U13.Y8(VCCE_GXBL) ; also on sheet 25 29 30
C5_VCCL_GXBL: U13.AA7(VCCL_GXBL) U13.AC7(VCCL_GXBL) U13.N7(VCCL_GXBL) U13.R7(VCCL_GXBL) U13.U7(VCCL_GXBL) U13.W7(VCCL_GXBL) ; also on sheet 25 30
DDR3A_A0: U13.AK18(HMC_B_A_0/DQ6B/DIFFIO_TX_B48p) ; also on sheet 12
DDR3A_A1: U13.AL18(HMC_B_A_1/DQ6B/DIFFIO_TX_B48n) ; also on sheet 12
DDR3A_A4: U13.AH17(HMC_B_A_4/DQ6B/DIFFIO_RX_B46p) ; also on sheet 12
DDR3A_A5: U13.AJ17(HMC_B_A_5/DQ6B/DIFFIO_RX_B46n) ; also on sheet 12
DDR3A_A6: U13.AK17(HMC_B_A_6/DIFFIO_TX_B44p) ; also on sheet 12
DDR3A_A7: U13.AL17(HMC_B_A_7/DQ6B/DIFFIO_TX_B44n) ; also on sheet 12
DDR3A_A8: U13.AH16(HMC_B_A_8/DQ5B/DIFFIO_RX_B38p) ; also on sheet 12
DDR3A_A9: U13.AJ16(HMC_B_A_9/DQ5B/DIFFIO_RX_B38n) ; also on sheet 12
DDR3A_A10: U13.AL16(HMC_B_A_10/DQ5B/DIFFIO_TX_B37p) ; also on sheet 12
DDR3A_A11: U13.AM16(HMC_B_A_11/DQ5B/DIFFIO_TX_B37n) ; also on sheet 12
DDR3A_A12: U13.AM13(HMC_B_A_12/DIFFIO_TX_B36p) ; also on sheet 12
DDR3A_A13: U13.AN13(HMC_B_A_13/DQ5B/DIFFIO_TX_B36n) ; also on sheet 12
DDR3A_BA0: U13.AN16(HMC_B_BA_0/DQ6B/DIFFIO_TX_B41p) ; also on sheet 12
DDR3A_BA1: U13.AN17(HMC_B_BA_1/DQ6B/DIFFIO_RX_B42p) ; also on sheet 12
DDR3A_BA2: U13.AP17(HMC_B_BA_2/DQ6B/DIFFIO_RX_B42n) ; also on sheet 12
DDR3A_CASn: U13.AP15(HMC_B_CASn/DQ5B/DIFFIO_TX_B40p) ; also on sheet 12
DDR3A_CKE: U13.AP26(HMC_B_CKE_0/DQ8B/DIFFIO_TX_B61n) ; also on sheet 12
DDR3A_CLK_N: U13.AA17(HMC_B_CKn/DQSn6B/DIFFIO_RX_B43n) ; also on sheet 12
DDR3A_CLK_P: U13.AA18(HMC_B_CK/DQS6B/DIFFIO_RX_B43p) ; also on sheet 12
DDR3A_CSn: U13.AA16(HMC_B_CSn_0/DQS5B/DIFFIO_RX_B35p) ; also on sheet 12
DDR3A_DM0: U13.AL21(HMC_B_DM_0/DQ7B/DIFFIO_TX_B56p) ; also on sheet 12
DDR3A_DM1: U13.AM24(HMC_B_DM_1/DQ8B/DIFFIO_TX_B64p) ; also on sheet 12
DDR3A_DM2: U13.AM28(HMC_B_DM_2/DQ9B/DIFFIO_TX_B72p) ; also on sheet 12
DDR3A_DM3: U13.AL27(HMC_B_DM_3/DQ10B/DIFFIO_TX_B80p) ; also on sheet 12
DDR3A_DM4: U13.AL30(HMC_B_DM_4/DQ11B/DIFFIO_TX_B88p) ; also on sheet 12
DDR3A_DQ0: U13.AN19(HMC_B_DQ_0/DQ7B/DIFFIO_RX_B50n) ; also on sheet 12
DDR3A_DQ1: U13.AM19(HMC_B_DQ_1/DQ7B/DIFFIO_RX_B50p) ; also on sheet 12
DDR3A_DQ2: U13.AP20(HMC_B_DQ_2/DQ7B/DIFFIO_TX_B49p) ; also on sheet 12
DDR3A_DQ3: U13.AP21(HMC_B_DQ_3/DQ7B/DIFFIO_TX_B52n) ; also on sheet 12
DDR3A_DQ4: U13.AH19(HMC_B_DQ_4/DQ7B/DIFFIO_RX_B54n) ; also on sheet 12
DDR3A_DQ5: U13.AG19(HMC_B_DQ_5/DQ7B/DIFFIO_RX_B54p) ; also on sheet 12
DDR3A_DQ6: U13.AJ19(HMC_B_DQ_6/DQ7B/DIFFIO_TX_B53p) ; also on sheet 12
DDR3A_DQ7: U13.AM21(HMC_B_DQ_7/DQ7B/DIFFIO_TX_B56n) ; also on sheet 12
DDR3A_DQ8: U13.AM20(HMC_B_DQ_8/DQ8B/DIFFIO_RX_B58n) ; also on sheet 12
DDR3A_DQ9: U13.AL20(HMC_B_DQ_9/DQ8B/DIFFIO_RX_B58p) ; also on sheet 12
DDR3A_DQ10: U13.AN22(HMC_B_DQ_10/DQ8B/DIFFIO_TX_B57p) ; also on sheet 12
DDR3A_DQ11: U13.AN23(HMC_B_DQ_11/DQ8B/DIFFIO_TX_B60n) ; also on sheet 12
DDR3A_DQ12: U13.AP24(HMC_B_DQ_12/DQ8B/DIFFIO_RX_B62n) ; also on sheet 12
DDR3A_DQ13: U13.AP25(HMC_B_DQ_13/DQ8B/DIFFIO_RX_B62p) ; also on sheet 12
DDR3A_DQ14: U13.AN26(HMC_B_DQ_14/DQ8B/DIFFIO_TX_B61p) ; also on sheet 12
DDR3A_DQ15: U13.AN24(HMC_B_DQ_15/DQ8B/DIFFIO_TX_B64n) ; also on sheet 12
DDR3A_DQ16: U13.AP27(HMC_B_DQ_16/DQ9B/DIFFIO_RX_B66n) ; also on sheet 12
DDR3A_DQ17: U13.AN27(HMC_B_DQ_17/DQ9B/DIFFIO_RX_B66p) ; also on sheet 12
DDR3A_DQ18: U13.AK22(HMC_B_DQ_18/DQ9B/DIFFIO_TX_B65p) ; also on sheet 12
DDR3A_DQ19: U13.AJ21(HMC_B_DQ_19/DQ9B/DIFFIO_TX_B68n) ; also on sheet 12
DDR3A_DQ20: U13.AH21(HMC_B_DQ_20/DQ9B/DIFFIO_RX_B70n) ; also on sheet 12
DDR3A_DQ21: U13.AH22(HMC_B_DQ_21/DQ9B/DIFFIO_RX_B70p) ; also on sheet 12
DDR3A_DQ22: U13.AP30(HMC_B_DQ_22/DQ9B/DIFFIO_TX_B69p) ; also on sheet 12
DDR3A_DQ23: U13.AN28(HMC_B_DQ_23/DQ9B/DIFFIO_TX_B72n) ; also on sheet 12
DDR3A_DQ24: U13.AL23(HMC_B_DQ_24/DQ10B/DIFFIO_RX_B74n) ; also on sheet 12
DDR3A_DQ25: U13.AK23(HMC_B_DQ_25/DQ10B/DIFFIO_RX_B74p) ; also on sheet 12
DDR3A_DQ26: U13.AL25(HMC_B_DQ_26/DQ10B/DIFFIO_TX_B73p) ; also on sheet 12
DDR3A_DQ27: U13.AM26(HMC_B_DQ_27/DQ10B/DIFFIO_TX_B76n) ; also on sheet 12
DDR3A_DQ28: U13.AK24(HMC_B_DQ_28/DQ10B/DIFFIO_RX_B78n) ; also on sheet 12
DDR3A_DQ29: U13.AJ24(HMC_B_DQ_29/DQ10B/DIFFIO_RX_B78p) ; also on sheet 12
DDR3A_DQ30: U13.AN31(HMC_B_DQ_30/DQ10B/DIFFIO_TX_B77p) ; also on sheet 12
DDR3A_DQ31: U13.AL28(HMC_B_DQ_31/DQ10B/DIFFIO_TX_B80n) ; also on sheet 12
DDR3A_DQ32: U13.AH23(HMC_B_DQ_32/DQ11B/DIFFIO_RX_B82n) ; also on sheet 12
DDR3A_DQ33: U13.AG23(HMC_B_DQ_33/DQ11B/DIFFIO_RX_B82p) ; also on sheet 12
DDR3A_DQ34: U13.AN32(HMC_B_DQ_34/DQ11B/DIFFIO_TX_B81p) ; also on sheet 12
DDR3A_DQ35: U13.AN29(HMC_B_DQ_35/DQ11B/DIFFIO_TX_B84n) ; also on sheet 12
DDR3A_DQ36: U13.AK25(HMC_B_DQ_36/DQ11B/DIFFIO_RX_B86n) ; also on sheet 12
DDR3A_DQ37: U13.AJ25(HMC_B_DQ_37/DQ11B/DIFFIO_RX_B86p) ; also on sheet 12
DDR3A_DQ38: U13.AK28(HMC_B_DQ_38/DQ11B/DIFFIO_TX_B85p) ; also on sheet 12
DDR3A_DQ39: U13.AM30(HMC_B_DQ_39/DQ11B/DIFFIO_TX_B88n) ; also on sheet 12
DDR3A_DQS_N0: U13.AC19(HMC_B_DQSn_0/DQSn7B/DIFFIO_RX_B51n) ; also on sheet 12
DDR3A_DQS_N1: U13.AE19(HMC_B_DQSn_1/DQSn8B/DIFFIO_RX_B59n) ; also on sheet 12
DDR3A_DQS_N2: U13.AK20(HMC_B_DQSn_2/DQSn9B/DIFFIO_RX_B67n) ; also on sheet 12
DDR3A_DQS_N3: U13.AA20(HMC_B_DQSn_3/DQSn10B/DIFFIO_RX_B75n) ; also on sheet 12
DDR3A_DQS_N4: U13.AD21(HMC_B_DQSn_4/DQSn11B/DIFFIO_RX_B83n) ; also on sheet 12
DDR3A_DQS_P0: U13.AB19(HMC_B_DQS_0/DQS7B/DIFFIO_RX_B51p) ; also on sheet 12
DDR3A_DQS_P1: U13.AD19(HMC_B_DQS_1/DQS8B/DIFFIO_RX_B59p) ; also on sheet 12
DDR3A_DQS_P2: U13.AJ20(HMC_B_DQS_2/DQS9B/DIFFIO_RX_B67p) ; also on sheet 12
DDR3A_DQS_P3: U13.Y20(HMC_B_DQS_3/DQS10B/DIFFIO_RX_B75p) ; also on sheet 12
DDR3A_DQS_P4: U13.AC21(HMC_B_DQS_4/DQS11B/DIFFIO_RX_B83p) ; also on sheet 12
DDR3A_ODT: U13.AN21(HMC_B_ODT_0/DIFFIO_TX_B52p) ; also on sheet 12
DDR3A_RASn: U13.AP14(HMC_B_RASn/DQ5B/DIFFIO_TX_B40n) ; also on sheet 12
DDR3A_RESETn: U13.AJ22(HMC_B_RESETn/DIFFIO_TX_B68p) ; also on sheet 12
DDR3A_WEn: U13.AN12(HMC_B_WEn/DQ5B/DIFFIO_TX_B33p) ; also on sheet 12
DDR3B_A0: U13.H29(DIFFIO_TX_R86p) ; also on sheet 13
DDR3B_A1: U13.K28(DIFFIO_TX_R88n) ; also on sheet 13
DDR3B_A2: U13.K34(DIFFIO_TX_R62p) ; also on sheet 13
DDR3B_A3: U13.L32(DIFFIO_TX_R64n) ; also on sheet 13
DDR3B_A4: U13.R32(DIFFIO_RX_R65p) ; also on sheet 13
DDR3B_A5: U13.R33(DIFFIO_RX_R65n) ; also on sheet 13
DDR3B_A6: U13.N32(DIFFIO_TX_R70p) ; also on sheet 13
DDR3B_A7: U13.G33(DIFFIO_TX_R72n) ; also on sheet 13
DDR3B_A8: U13.AE34(DIFFIO_TX_R46p) ; also on sheet 13
DDR3B_A9: U13.L27(DQ11R/DIFFIO_RX_R87n) ; also on sheet 13
DDR3B_A10: U13.V33(DIFFIO_TX_R54p) ; also on sheet 13
DDR3B_A11: U13.U33(DIFFIO_TX_R56n) ; also on sheet 13
DDR3B_BA0: U13.J31(DIFFIO_TX_R78p) ; also on sheet 13
DDR3B_BA1: U13.N29(DIFFIO_TX_R80n) ; also on sheet 13
DDR3B_BA2: U13.P27(DIFFIO_RX_R81p) ; also on sheet 13
DDR3B_CASn: U13.N27(DIFFIO_RX_R81n) ; also on sheet 13
DDR3B_CKE: U13.AF32(DIFFIO_TX_R40n) ; also on sheet 13
DDR3B_CLK_N: U13.R29(DIFFIO_RX_R73n) ; also on sheet 13
DDR3B_CLK_P: U13.R30(DIFFIO_RX_R73p) ; also on sheet 13
DDR3B_DM0: U13.AE30(DQ4R/DIFFIO_TX_R26p) ; also on sheet 13
DDR3B_DM1: U13.AE32(DQ5R/DIFFIO_TX_R40p) ; also on sheet 13
DDR3B_DM2: U13.AC34(DQ6R/DIFFIO_RX_R43n) ; also on sheet 13
DDR3B_DM4: U13.M33(DQ8R/DIFFIO_TX_R60n) ; also on sheet 13
DDR3B_DM5: U13.K32(DQ9R/DIFFIO_TX_R66n) ; also on sheet 13
DDR3B_DM6: U13.L31(DQ10R/DIFFIO_TX_R74n) ; also on sheet 13
DDR3B_DM7: U13.H28(DQ11R/DIFFIO_TX_R86n) ; also on sheet 13
DDR3B_DQ0: U13.AF31(DQ4R/DIFFIO_TX_R30n) ; also on sheet 13
DDR3B_DQ1: U13.AD30(DQ4R/DIFFIO_TX_R26n) ; also on sheet 13
DDR3B_DQ2: U13.AJ32(DQ4R/DIFFIO_TX_R28n) ; also on sheet 13
DDR3B_DQ3: U13.AC31(DQ4R/DIFFIO_RX_R31p) ; also on sheet 13
DDR3B_DQ4: U13.AH32(DQ4R/DIFFIO_TX_R28p) ; also on sheet 13
DDR3B_DQ5: U13.Y28(DQ4R/DIFFIO_RX_R27p) ; also on sheet 13
DDR3B_DQ6: U13.AN34(DQ4R/DIFFIO_TX_R32p) ; also on sheet 13
DDR3B_DQ7: U13.Y27(DQ4R/DIFFIO_RX_R27n) ; also on sheet 13
DDR3B_DQ8: U13.AD32(DQ5R/DIFFIO_TX_R38n) ; also on sheet 13
DDR3B_DQ9: U13.AH33(DQ5R/DIFFIO_TX_R36p) ; also on sheet 13
DDR3B_DQ10: U13.AB31(DQ5R/DIFFIO_TX_R34n) ; also on sheet 13
DDR3B_DQ11: U13.AJ34(DQ5R/DIFFIO_RX_R35n) ; also on sheet 13
DDR3B_DQ12: U13.AA31(DQ5R/DIFFIO_TX_R34p) ; also on sheet 13
DDR3B_DQ13: U13.AK34(DQ5R/DIFFIO_RX_R35p) ; also on sheet 13
DDR3B_DQ14: U13.W31(DQ5R/DIFFIO_RX_R39p) ; also on sheet 13
DDR3B_DQ15: U13.AG33(DQ5R/DIFFIO_TX_R36n) ; also on sheet 13
DDR3B_DQ16: U13.AD34(DQ6R/DIFFIO_TX_R46n) ; also on sheet 13
DDR3B_DQ17: U13.AC33(DQ6R/DIFFIO_RX_R43p) ; also on sheet 13
DDR3B_DQ18: U13.AG34(DQ6R/DIFFIO_TX_R42p) ; also on sheet 13
DDR3B_DQ19: U13.AB33(DQ6R/DIFFIO_TX_R48p) ; also on sheet 13
DDR3B_DQ21: U13.V32(DQ6R/DIFFIO_RX_R47n) ; also on sheet 13
DDR3B_DQ22: U13.AH34(DQ6R/DIFFIO_TX_R42n) ; also on sheet 13
DDR3B_DQ23: U13.W32(DQ6R/DIFFIO_RX_R47p) ; also on sheet 13
DDR3B_DQ24: U13.U29(DQ7R/DIFFIO_RX_R51n) ; also on sheet 13
DDR3B_DQ25: U13.V34(DQ7R/DIFFIO_TX_R54n) ; also on sheet 13
DDR3B_DQ26: U13.U34(DQ7R/DIFFIO_TX_R56p) ; also on sheet 13
DDR3B_DQ27: U13.AA33(DQ7R/DIFFIO_TX_R50n) ; also on sheet 13
DDR3B_DQ28: U13.R34(DQ7R/DIFFIO_RX_R55p) ; also on sheet 13
DDR3B_DQ29: U13.Y33(DQ7R/DIFFIO_TX_R50p) ; also on sheet 13
DDR3B_DQ30: U13.P34(DQ7R/DIFFIO_RX_R55n) ; also on sheet 13
DDR3B_DQ31: U13.U28(DQ7R/DIFFIO_RX_R51p) ; also on sheet 13
DDR3B_DQ32: U13.T32(DQ8R/DIFFIO_TX_R58n) ; also on sheet 13
DDR3B_DQ33: U13.N33(DQ8R/DIFFIO_RX_R63p) ; also on sheet 13
DDR3B_DQ34: U13.T33(DQ8R/DIFFIO_TX_R58p) ; also on sheet 13
DDR3B_DQ35: U13.L33(DQ8R/DIFFIO_TX_R64p) ; also on sheet 13
DDR3B_DQ36: U13.T28(DQ8R/DIFFIO_RX_R59n) ; also on sheet 13
DDR3B_DQ37: U13.J34(DQ8R/DIFFIO_TX_R62n) ; also on sheet 13
DDR3B_DQ38: U13.T27(DQ8R/DIFFIO_RX_R59p) ; also on sheet 13
DDR3B_DQ39: U13.M34(DQ8R/DIFFIO_TX_R60p) ; also on sheet 13
DDR3B_DQ40: U13.K33(DQ9R/DIFFIO_TX_R66p) ; also on sheet 13
DDR3B_DQ41: U13.N31(DQ9R/DIFFIO_TX_R70n) ; also on sheet 13
DDR3B_DQ42: U13.G34(DQ9R/DIFFIO_TX_R72p) ; also on sheet 13
DDR3B_DQ43: U13.R28(DQ9R/DIFFIO_RX_R67n) ; also on sheet 13
DDR3B_DQ44: U13.H33(DQ9R/DIFFIO_TX_R68n) ; also on sheet 13
DDR3B_DQ45: U13.P32(DQ9R/DIFFIO_RX_R71p) ; also on sheet 13
DDR3B_DQ46: U13.H34(DQ9R/DIFFIO_TX_R68p) ; also on sheet 13
DDR3B_DQ47: U13.R27(DQ9R/DIFFIO_RX_R67p) ; also on sheet 13
DDR3B_DQ48: U13.N28(DQ10R/DIFFIO_RX_R79p) ; also on sheet 13
DDR3B_DQ49: U13.L30(DQ10R/DIFFIO_RX_R75p) ; also on sheet 13
DDR3B_DQ50: U13.P30(DQ10R/DIFFIO_TX_R80p) ; also on sheet 13
DDR3B_DQ51: U13.K30(DQ10R/DIFFIO_RX_R75n) ; also on sheet 13
DDR3B_DQ52: U13.J32(DQ10R/DIFFIO_TX_R76p) ; also on sheet 13
DDR3B_DQ53: U13.H32(DQ10R/DIFFIO_TX_R76n) ; also on sheet 13
DDR3B_DQ54: U13.M31(DQ10R/DIFFIO_TX_R74p) ; also on sheet 13
DDR3B_DQ55: U13.H31(DQ10R/DIFFIO_TX_R78n) ; also on sheet 13
DDR3B_DQ56: U13.G30(DQ11R/DIFFIO_TX_R82n) ; also on sheet 13
DDR3B_DQ57: U13.K29(DQ11R/DIFFIO_TX_R88p) ; also on sheet 13
DDR3B_DQ58: U13.G31(DQ11R/DIFFIO_TX_R82p) ; also on sheet 13
DDR3B_DQ59: U13.M30(DQ11R/DIFFIO_RX_R83n) ; also on sheet 13
DDR3B_DQ60: U13.J30(DQ11R/DIFFIO_TX_R84p) ; also on sheet 13
DDR3B_DQ61: U13.M29(DQ11R/DIFFIO_RX_R83p) ; also on sheet 13
DDR3B_DQ62: U13.J29(DQ11R/DIFFIO_TX_R84n) ; also on sheet 13
DDR3B_DQ63: U13.L28(DQ11R/DIFFIO_RX_R87p) ; also on sheet 13
DDR3B_DQS_N0: U13.Y30(DQSn4R/DIFFIO_RX_R29n) ; also on sheet 13
DDR3B_DQS_N1: U13.W30(DQSn5R/DIFFIO_RX_R37n) ; also on sheet 13
DDR3B_DQS_N2: U13.V23(DQSn6R/DIFFIO_RX_R45n) ; also on sheet 13
DDR3B_DQS_N3: U13.U25(DQSn7R/DIFFIO_RX_R53n) ; also on sheet 13
DDR3B_DQS_N4: U13.T23(DQSn8R/DIFFIO_RX_R61n) ; also on sheet 13
DDR3B_DQS_N5: U13.R25(DQSn9R/DIFFIO_RX_R69n) ; also on sheet 13
DDR3B_DQS_N6: U13.R24(DQSn10R/DIFFIO_RX_R77n) ; also on sheet 13
DDR3B_DQS_N7: U13.P25(DQSn11R/DIFFIO_RX_R85n) ; also on sheet 13
DDR3B_DQS_P0: U13.Y29(DQS4R/DIFFIO_RX_R29p) ; also on sheet 13
DDR3B_DQS_P1: U13.W29(DQS5R/DIFFIO_RX_R37p) ; also on sheet 13
DDR3B_DQS_P2: U13.V24(DQS6R/DIFFIO_RX_R45p) ; also on sheet 13
DDR3B_DQS_P3: U13.U24(DQS7R/DIFFIO_RX_R53p) ; also on sheet 13
DDR3B_DQS_P4: U13.U23(DQS8R/DIFFIO_RX_R61p) ; also on sheet 13
DDR3B_DQS_P5: U13.T25(DQS9R/DIFFIO_RX_R69p) ; also on sheet 13
DDR3B_DQS_P6: U13.R23(DQS10R/DIFFIO_RX_R77p) ; also on sheet 13
DDR3B_DQS_P7: U13.P24(DQS11R/DIFFIO_RX_R85p) ; also on sheet 13
DDR3B_ODT: U13.AA32(DIFFIO_RX_R25p) ; also on sheet 13
DDR3B_RASn: U13.Y32(DIFFIO_RX_R25n) ; also on sheet 13
DDR3B_RESETn: U13.AG31(DIFFIO_TX_R30p) ; also on sheet 13
DDR3B_WEn: U13.AM34(DIFFIO_TX_R32n) ; also on sheet 13
DISP_I2C_SCL: U13.AL6(DQ2B/DIFFIO_TX_B9p) ; also on sheet 20
DISP_I2C_SDA: U13.AJ10(DQ2B/DIFFIO_RX_B10p) ; also on sheet 20
DISP_SPISS: U13.AH13(DQ2B/DIFFIO_RX_B14p) ; also on sheet 20
ENET_GTX_CLK: U13.AP7(DQ2B/DIFFIO_TX_B16n) ; also on sheet 17
ENET_INTn: U13.AK10(DQ2B/DIFFIO_RX_B10n) ; also on sheet 17
ENET_MDC: U13.AM8(DQ3B/DIFFIO_TX_B17p) ; also on sheet 17
ENET_MDIO: U13.AG14(DQ3B/DIFFIO_RX_B18p) ; also on sheet 17
ENET_RESETn: U13.AN9(DQ3B/DIFFIO_TX_B20n) ; also on sheet 17
ENET_RX_CLK: U13.AM10(DQ3B/DIFFIO_TX_B21n) ; also on sheet 17
ENET_RX_D0: U13.AK14(DQ3B/DIFFIO_RX_B22n) ; also on sheet 17
ENET_RX_D1: U13.AL10(DQ3B/DIFFIO_TX_B21p) ; also on sheet 17
ENET_RX_D2: U13.AJ14(DQ3B/DIFFIO_RX_B22p) ; also on sheet 17
ENET_RX_D3: U13.AK12(DQ3B/DIFFIO_TX_B24n) ; also on sheet 17
ENET_RX_DV: U13.AH14(DQ3B/DIFFIO_RX_B18n) ; also on sheet 17
ENET_TX_D0: U13.AB14(DQS2B/DIFFIO_RX_B11p) ; also on sheet 17
ENET_TX_D1: U13.AD15(DQS3B/DIFFIO_RX_B19p) ; also on sheet 17
ENET_TX_D2: U13.AB15(DIFFIO_RX_B23n) ; also on sheet 17
ENET_TX_D3: U13.AB13(DQSn2B/DIFFIO_RX_B11n) ; also on sheet 17
ENET_TX_EN: U13.AC14(DQSn3B/DIFFIO_RX_B19n) ; also on sheet 17
FLASH_ADVn: U13.AB34(DIFFIO_TX_R48n) ; also on sheet 14 15
FLASH_OEn: U13.AG16(DQS4B/DIFFIO_RX_B27p) ; also on sheet 14 15
FLASH_RESETn: U13.AB16(HMC_B_CSn_1/DQSn5B/DIFFIO_RX_B35n) ; also on sheet 14 15
FLASH_WEn: U13.AM14(HMC_B_A_14/DQ5B/DIFFIO_RX_B34p) ; also on sheet 14 15
FM_A1: U13.AK33(DIFFIO_TX_R24n) ; also on sheet 14 15
FM_A3: U13.AB24(DQ1R/DIFFIO_RX_R4p) ; also on sheet 14 15
FM_A4: U13.AB23(DQ1R/DIFFIO_RX_R4n) ; also on sheet 14 15
FM_A5: U13.AC28(DQ1R/DIFFIO_TX_R7p) ; also on sheet 14 15
FM_A6: U13.Y24(DQ1R/DIFFIO_RX_R8p) ; also on sheet 14 15
FM_A7: U13.Y25(DQ1R/DIFFIO_RX_R8n) ; also on sheet 14 15
FM_A8: U13.AF27(DQ2R/DIFFIO_TX_R10p) ; also on sheet 14 15
FM_A9: U13.AF26(DQ2R/DIFFIO_TX_R10n) ; also on sheet 14 15
FM_A10: U13.AB28(DQ2R/DIFFIO_RX_R11p) ; also on sheet 14 15
FM_A11: U13.AE28(DQ2R/DIFFIO_TX_R12p) ; also on sheet 14 15
FM_A12: U13.AB29(DQ2R/DIFFIO_RX_R11n) ; also on sheet 14 15
FM_A13: U13.AF28(DQ2R/DIFFIO_TX_R12n) ; also on sheet 14 15
FM_A14: U13.AH28(DQ2R/DIFFIO_TX_R14n) ; also on sheet 14 15
FM_A15: U13.AB30(DQ2R/DIFFIO_RX_R15p) ; also on sheet 14 15
FM_A16: U13.AG29(DQ2R/DIFFIO_TX_R16p) ; also on sheet 14 15
FM_A17: U13.AA30(DQ2R/DIFFIO_RX_R15n) ; also on sheet 14 15
FM_A18: U13.AK30(DQ3R/DIFFIO_TX_R18p) ; also on sheet 14 15
FM_A19: U13.AJ30(DQ3R/DIFFIO_TX_R18n) ; also on sheet 14 15
FM_A20: U13.AG30(DQ3R/DIFFIO_RX_R19p) ; also on sheet 14 15
FM_A21: U13.AN33(DQ3R/DIFFIO_TX_R20p) ; also on sheet 14 15
FM_A22: U13.AF30(DQ3R/DIFFIO_RX_R19n) ; also on sheet 14 15
FM_A23: U13.AM33(DQ3R/DIFFIO_TX_R20n) ; also on sheet 14 15
FM_A24: U13.AK32(DQ3R/DIFFIO_TX_R22n) ; also on sheet 14 15
FM_A25: U13.AH31(DQ3R/DIFFIO_RX_R23p) ; also on sheet 14 15
FM_A26: U13.AD24(DQ1R/RZQ_1/DIFFIO_TX_R1p) ; also on sheet 14 15
FM_D0: U13.W24(DQSn3R/DIFFIO_RX_R21n) ; also on sheet 14 15
FM_D1: U13.AJ31(DQ3R/DIFFIO_RX_R23n) ; also on sheet 14 15
FM_D2: U13.Y22(DQSn2R/DIFFIO_RX_R13n) ; also on sheet 14 15
FM_D3: U13.AC29(DIFFIO_TX_R7n) ; also on sheet 14 15
FM_D4: U13.AB25(DIFFIO_RX_R9p) ; also on sheet 14 15
FM_D5: U13.AA23(DQS2R/DIFFIO_RX_R13p) ; also on sheet 14 15
FM_D6: U13.AA25(DIFFIO_RX_R9n) ; also on sheet 14 15
FM_D7: U13.Y23(DQS3R/DIFFIO_RX_R21p) ; also on sheet 14 15
FM_D8: U13.AH29(DIFFIO_TX_R16n) ; also on sheet 14 15
FM_D9: U13.AA28(DIFFIO_RX_R17n) ; also on sheet 14 15
FM_D10: U13.AL33(DQ3R/DIFFIO_TX_R24p) ; also on sheet 14 15
FM_D11: U13.AA27(DIFFIO_RX_R17p) ; also on sheet 14 15
FM_D12: U13.AL32(DIFFIO_TX_R22p) ; also on sheet 14 15
FM_D14: U13.AG28(DIFFIO_TX_R14p) ; also on sheet 14 15
HSMA_CLK_IN0: U13.G11(DQ12T/DIFFIO_RX_T95n) ; also on sheet 18
HSMA_CLK_OUT0: U13.F10(DQ12T/DIFFIO_TX_T90p) ; also on sheet 18
HSMA_CLK_OUT_N1: U13.B1(DIFFIO_TX_T88n) ; also on sheet 18
HSMA_CLK_OUT_P1: U13.C1(DQ11T/DIFFIO_TX_T88p) ; also on sheet 18
HSMA_D0: U13.L12(DIFFIO_RX_T89p) ; also on sheet 18
HSMA_D1: U13.F11(DQ12T/DIFFIO_RX_T91n) ; also on sheet 18
HSMA_D2: U13.F12(DQ12T/DIFFIO_RX_T91p) ; also on sheet 18
HSMA_D3: U13.K12(DQSn12T/DIFFIO_RX_T93n) ; also on sheet 18
HSMA_JTAG_EN: R73.1 SW3.5(B4) ; also on sheet 11
HSMA_PRSNTn: U13.L11(DQS12T/DIFFIO_RX_T93p) ; also on sheet 15 18 20
HSMA_RX_D_N0: U13.N14(DQSn10T/DIFFIO_RX_T77n) ; also on sheet 18
HSMA_RX_D_N1: U13.M14(HMC_T_CSn_1/DQSn8T/DIFFIO_RX_T61n) ; also on sheet 18
HSMA_RX_D_N2: U13.L13(DIFFIO_RX_T81n) ; also on sheet 18
HSMA_RX_D_N3: U13.N12(DQSn11T/DIFFIO_RX_T85n) ; also on sheet 18
HSMA_RX_D_N4: U13.L17(HMC_T_CKn/DQSn7T/DIFFIO_RX_T53n) ; also on sheet 18
HSMA_RX_D_N5: U13.A8(DQ9T/DIFFIO_RX_T67n) ; also on sheet 18
HSMA_RX_D_N6: U13.K14(DIFFIO_RX_T73n) ; also on sheet 18
HSMA_RX_D_N7: U13.G14(DQ10T/DIFFIO_RX_T79n) ; also on sheet 18
HSMA_RX_D_N8: U13.D15(DQ9T/DIFFIO_RX_T71n) ; also on sheet 18
HSMA_RX_D_N9: U13.G15(DIFFIO_RX_T65n) ; also on sheet 18
HSMA_RX_D_N10: U13.E17(HMC_T_A_5/DQ7T/DIFFIO_RX_T51n) ; also on sheet 18
HSMA_RX_D_N11: U13.H13(DQ11T/DIFFIO_RX_T83n) ; also on sheet 18
HSMA_RX_D_N12: U13.D14(DQ10T/DIFFIO_RX_T75n) ; also on sheet 18
HSMA_RX_D_N13: U13.B16(HMC_T_BA_2/DQ7T/DIFFIO_RX_T55n) ; also on sheet 18
HSMA_RX_D_N14: U13.D16(HMC_T_A_15/DQ8T/DIFFIO_RX_T63n) ; also on sheet 18
HSMA_RX_D_N15: U13.L15(DQSn9T/DIFFIO_RX_T69n) ; also on sheet 18
HSMA_RX_D_N16: U13.F16(HMC_T_A_9/DQ8T/DIFFIO_RX_T59n) ; also on sheet 18
HSMA_RX_D_P0: U13.P14(DQS10T/DIFFIO_RX_T77p) ; also on sheet 18
HSMA_RX_D_P1: U13.M15(HMC_T_CSn_0/DQS8T/DIFFIO_RX_T61p) ; also on sheet 18
HSMA_RX_D_P2: U13.M13(DIFFIO_RX_T81p) ; also on sheet 18
HSMA_RX_D_P3: U13.N13(DQS11T/DIFFIO_RX_T85p) ; also on sheet 18
HSMA_RX_D_P4: U13.M16(HMC_T_CK/DQS7T/DIFFIO_RX_T53p) ; also on sheet 18
HSMA_RX_D_P5: U13.B8(DQ9T/DIFFIO_RX_T67p) ; also on sheet 18
HSMA_RX_D_P6: U13.J15(DIFFIO_RX_T73p) ; also on sheet 18
HSMA_RX_D_P7: U13.H14(DQ10T/DIFFIO_RX_T79p) ; also on sheet 18
HSMA_RX_D_P8: U13.E15(DQ9T/DIFFIO_RX_T71p) ; also on sheet 18
HSMA_RX_D_P9: U13.F15(DIFFIO_RX_T65p) ; also on sheet 18
HSMA_RX_D_P10: U13.E18(HMC_T_A_4/DQ7T/DIFFIO_RX_T51p) ; also on sheet 18
HSMA_RX_D_P11: U13.G13(DQ11T/DIFFIO_RX_T83p) ; also on sheet 18
HSMA_RX_D_P12: U13.E14(DQ10T/DIFFIO_RX_T75p) ; also on sheet 18
HSMA_RX_D_P13: U13.C16(HMC_T_BA_1/DQ7T/DIFFIO_RX_T55p) ; also on sheet 18
HSMA_RX_D_P14: U13.D17(HMC_T_A_14/DQ8T/DIFFIO_RX_T63p) ; also on sheet 18
HSMA_RX_D_P15: U13.L16(DQS9T/DIFFIO_RX_T69p) ; also on sheet 18
HSMA_RX_D_P16: U13.F17(HMC_T_A_8/DQ8T/DIFFIO_RX_T59p) ; also on sheet 18
HSMA_RX_LED: U13.D12(DQ11T/DIFFIO_RX_T87n) ; also on sheet 20
HSMA_RX_N0: U13.AA1(GXB_RX_L4n,GXB_REFCLK_L4n) ; also on sheet 18
HSMA_RX_N1: U13.W1(GXB_RX_L5n,GXB_REFCLK_L5n) ; also on sheet 18
HSMA_RX_N2: U13.U1(GXB_RX_L6n,GXB_REFCLK_L6n) ; also on sheet 18
HSMA_RX_N3: R48.1 ; also on sheet 18
HSMA_RX_P0: U13.AA2(GXB_RX_L4p,GXB_REFCLK_L4p) ; also on sheet 18
HSMA_RX_P1: U13.W2(GXB_RX_L5p,GXB_REFCLK_L5p) ; also on sheet 18
HSMA_RX_P2: U13.U2(GXB_RX_L6p,GXB_REFCLK_L6p) ; also on sheet 18
HSMA_RX_P3: R47.1 ; also on sheet 18
HSMA_SCL: U13.E12(DQ11T/DIFFIO_RX_T87p) ; also on sheet 18
HSMA_SDA: U13.K13(DIFFIO_RX_T89n) ; also on sheet 18
HSMA_TX_D_N0: U13.A3(DIFFIO_TX_T80n) ; also on sheet 18
HSMA_TX_D_N1: U13.B9(DQ9T/DIFFIO_TX_T70n) ; also on sheet 18
HSMA_TX_D_N2: U13.A5(DQ10T/DIFFIO_TX_T74n) ; also on sheet 18
HSMA_TX_D_N3: U13.A11(HMC_T_RASn/DQ8T/DIFFIO_TX_T58n) ; also on sheet 18
HSMA_TX_D_N4: U13.B6(DQ10T/DIFFIO_TX_T76n) ; also on sheet 18
HSMA_TX_D_N5: U13.C12(DIFFIO_TX_T72n) ; also on sheet 18
HSMA_TX_D_N6: U13.A6(DQ9T/DIFFIO_TX_T66n) ; also on sheet 18
HSMA_TX_D_N7: U13.C7(DQ11T/DIFFIO_TX_T84n) ; also on sheet 18
HSMA_TX_D_N8: U13.D10(DQ11T/DIFFIO_TX_T82n) ; also on sheet 18
HSMA_TX_D_N9: U13.A10(HMC_GND/DIFFIO_TX_T64n) ; also on sheet 18
HSMA_TX_D_N10: U13.A13(HMC_T_A_11/DQ8T/DIFFIO_TX_T60n) ; also on sheet 18
HSMA_TX_D_N11: U13.B11(DQ9T/DIFFIO_TX_T68n) ; also on sheet 18
HSMA_TX_D_N12: U13.B14(HMC_T_A_13/DQ8T/DIFFIO_TX_T62n) ; also on sheet 18
HSMA_TX_D_N13: U13.E13(DQ10T/DIFFIO_TX_T78n) ; also on sheet 18
HSMA_TX_D_N14: U13.A16(HMC_T_A_7/DQ7T/DIFFIO_TX_T54n) ; also on sheet 18
HSMA_TX_D_N15: U13.A15(HMC_GND/DIFFIO_TX_T56n) ; also on sheet 18
HSMA_TX_D_N16: U13.C17(HMC_T_A_1/DQ7T/DIFFIO_TX_T50n) ; also on sheet 18
HSMA_TX_D_P0: U13.B4(DQ10T/DIFFIO_TX_T80p) ; also on sheet 18
HSMA_TX_D_P1: U13.C9(DIFFIO_TX_T70p) ; also on sheet 18
HSMA_TX_D_P2: U13.B5(DQ10T/DIFFIO_TX_T74p) ; also on sheet 18
HSMA_TX_D_P3: U13.A12(HMC_T_CASn/DQ8T/DIFFIO_TX_T58p) ; also on sheet 18
HSMA_TX_D_P4: U13.C6(DQ10T/DIFFIO_TX_T76p) ; also on sheet 18
HSMA_TX_D_P5: U13.C13(DQ9T/DIFFIO_TX_T72p) ; also on sheet 18
HSMA_TX_D_P6: U13.A7(DQ9T/DIFFIO_TX_T66p) ; also on sheet 18
HSMA_TX_D_P7: U13.C8(DQ11T/DIFFIO_TX_T84p) ; also on sheet 18
HSMA_TX_D_P8: U13.D11(DQ11T/DIFFIO_TX_T82p) ; also on sheet 18
HSMA_TX_D_P9: U13.B10(HMC_T_WEn/DQ8T/DIFFIO_TX_T64p) ; also on sheet 18
HSMA_TX_D_P10: U13.B13(HMC_T_A_10/DQ8T/DIFFIO_TX_T60p) ; also on sheet 18
HSMA_TX_D_P11: U13.C11(DQ9T/DIFFIO_TX_T68p) ; also on sheet 18
HSMA_TX_D_P12: U13.C14(HMC_T_A_12/DIFFIO_TX_T62p) ; also on sheet 18
HSMA_TX_D_P13: U13.F13(DIFFIO_TX_T78p) ; also on sheet 18
HSMA_TX_D_P14: U13.A17(HMC_T_A_6/DIFFIO_TX_T54p) ; also on sheet 18
HSMA_TX_D_P15: U13.B15(HMC_T_BA_0/DQ7T/DIFFIO_TX_T56p) ; also on sheet 18
HSMA_TX_D_P16: U13.C18(HMC_T_A_0/DQ7T/DIFFIO_TX_T50p) ; also on sheet 18
HSMA_TX_LED: U13.B3(DQ11T/DIFFIO_TX_T86n) ; also on sheet 20
HSMA_TX_N0: U13.Y3(GXB_TX_L4n) ; also on sheet 18
HSMA_TX_N1: U13.V3(GXB_TX_L5n) ; also on sheet 18
HSMA_TX_N2: U13.T3(GXB_TX_L6n) ; also on sheet 18
HSMA_TX_N3: R42.1 ; also on sheet 18
HSMA_TX_P0: U13.Y4(GXB_TX_L4p) ; also on sheet 18
HSMA_TX_P1: U13.V4(GXB_TX_L5p) ; also on sheet 18
HSMA_TX_P2: U13.T4(GXB_TX_L6p) ; also on sheet 18
HSMA_TX_P3: R41.1 ; also on sheet 18
HSMB_A0: U13.E23(HMC_T_DQ_23/DQ4T/DIFFIO_TX_T26n) ; also on sheet 18
HSMB_A1: U13.B25(HMC_T_CKE_0/DQ5T/DIFFIO_TX_T36n) ; also on sheet 18
HSMB_A2: U13.A28(HMC_T_DM_1/DQ5T/DIFFIO_TX_T34p) ; also on sheet 18
HSMB_A3: U13.A26(HMC_T_DQ_10/DQ5T/DIFFIO_TX_T40p) ; also on sheet 18
HSMB_A4: U13.D21(HMC_T_DQ_11/DQ5T/DIFFIO_TX_T38n) ; also on sheet 18
HSMB_A5: U13.C23(HMC_T_DQ_12/DQ5T/DIFFIO_RX_T35n) ; also on sheet 18
HSMB_A6: U13.E29(HMC_GND/DIFFIO_TX_T14p) ; also on sheet 18
HSMB_A7: U13.D22(HMC_T_DQ_13/DQ5T/DIFFIO_RX_T35p) ; also on sheet 18
HSMB_A8: U13.D19(HMC_T_DQ_3/DQ6T/DIFFIO_TX_T46n) ; also on sheet 18
HSMB_A9: U13.B21(HMC_T_DQ_4/DQ6T/DIFFIO_RX_T43n) ; also on sheet 18
HSMB_A10: U13.E20(HMC_T_DQ_9/DQ5T/DIFFIO_RX_T39p) ; also on sheet 18
HSMB_A11: U13.B23(HMC_T_DM_0/DQ6T/DIFFIO_TX_T42p) ; also on sheet 18
HSMB_A12: U13.L25(HMC_GND/DIFFIO_RX_T9n) ; also on sheet 18
HSMB_A13: U13.B19(HMC_T_DQ_0/DQ6T/DIFFIO_RX_T47n) ; also on sheet 18
HSMB_A14: U13.B20(HMC_T_DQ_1/DQ6T/DIFFIO_RX_T47p) ; also on sheet 18
HSMB_A15: U13.A21(HMC_T_DQ_2/DQ6T/DIFFIO_TX_T48p) ; also on sheet 18
HSMB_ADDR_CMD0: U13.L18(HMC_T_DQSn_0/DQSn6T/DIFFIO_RX_T45n) ; also on sheet 18
HSMB_BA0: U13.B26(HMC_T_DQ_14/DQ5T/DIFFIO_TX_T36p) ; also on sheet 18
HSMB_BA1: U13.A27(HMC_T_DQ_15/DQ5T/DIFFIO_TX_T34n) ; also on sheet 18
HSMB_BA2: U13.D20(HMC_T_DQ_8/DQ5T/DIFFIO_RX_T39n) ; also on sheet 18
HSMB_BA3: U13.M19(HMC_T_DQSn_1/DQSn5T/DIFFIO_RX_T37n) ; also on sheet 18
HSMB_C_N: U13.E19(HMC_T_ODT_0/DIFFIO_TX_T46p) ; also on sheet 18
HSMB_C_P: U13.M18(HMC_T_DQS_0/DQS6T/DIFFIO_RX_T45p) ; also on sheet 18
HSMB_CASn: U13.C21(HMC_T_DQ_5/DQ6T/DIFFIO_RX_T43p) ; also on sheet 18
HSMB_CKE: U13.C22(HMC_T_CKE_1/DIFFIO_TX_T38p) ; also on sheet 18
HSMB_CLK_IN0: U13.A22(HMC_T_ODT_1/DQ6T/DIFFIO_TX_T44n) ; also on sheet 18
HSMB_CLK_IN_N1: U13.J25(DIFFIO_RX_T1n) ; also on sheet 18
HSMB_CLK_IN_P1: U13.K25(DIFFIO_RX_T1p) ; also on sheet 18
HSMB_CLK_OUT0: U13.D25(HMC_T_RESETn/DIFFIO_TX_T30p) ; also on sheet 18
HSMB_CLK_OUT_N1: U13.K22(HMC_GND/DIFFIO_RX_T17n) ; also on sheet 18
HSMB_CLK_OUT_N2: U13.G26(DQ1T/DIFFIO_TX_T6n) ; also on sheet 18
HSMB_CLK_OUT_P1: U13.L22(HMC_GND/DIFFIO_RX_T17p) ; also on sheet 18
HSMB_CLK_OUT_P2: U13.F26(DIFFIO_TX_T6p) ; also on sheet 18
HSMB_CSn: U13.M25(HMC_GND/DIFFIO_RX_T9p) ; also on sheet 18
HSMB_DM0: U13.C27(HMC_GND/DQ4T/DIFFIO_TX_T28n) ; also on sheet 18
HSMB_DM1: U13.C28(HMC_GND/DQ3T/DIFFIO_TX_T20n) ; also on sheet 18
HSMB_DM2: U13.C31(HMC_GND/DQ2T/DIFFIO_TX_T12n) ; also on sheet 18
HSMB_DM3: U13.H27(DQ1T/DIFFIO_TX_T2p) ; also on sheet 18
HSMB_DQ0: U13.E22(HMC_T_DM_2/DQ4T/DIFFIO_TX_T26p) ; also on sheet 18
HSMB_DQ1: U13.G20(HMC_T_DQ_16/DQ4T/DIFFIO_RX_T31n) ; also on sheet 18
HSMB_DQ2: U13.F20(HMC_T_DQ_17/DQ4T/DIFFIO_RX_T31p) ; also on sheet 18
HSMB_DQ3: U13.D24(HMC_T_DQ_18/DQ4T/DIFFIO_TX_T32p) ; also on sheet 18
HSMB_DQ4: U13.C26(HMC_T_DQ_19/DQ4T/DIFFIO_TX_T30n) ; also on sheet 18
HSMB_DQ5: U13.G21(HMC_T_DQ_20/DQ4T/DIFFIO_RX_T27n) ; also on sheet 18
HSMB_DQ6: U13.F21(HMC_T_DQ_21/DQ4T/DIFFIO_RX_T27p) ; also on sheet 18
HSMB_DQ7: U13.D27(HMC_T_DQ_22/DQ4T/DIFFIO_TX_T28p) ; also on sheet 18
HSMB_DQ8: U13.F23(HMC_T_DQ_29/DQ3T/DIFFIO_RX_T19p) ; also on sheet 18
HSMB_DQ9: U13.C29(HMC_T_DQ_30/DQ3T/DIFFIO_TX_T20p) ; also on sheet 18
HSMB_DQ10: U13.E24(HMC_T_DM_3/DQ3T/DIFFIO_TX_T18p) ; also on sheet 18
HSMB_DQ11: U13.H21(HMC_T_DQ_24/DQ3T/DIFFIO_RX_T23n) ; also on sheet 18
HSMB_DQ12: U13.H22(HMC_T_DQ_25/DQ3T/DIFFIO_RX_T23p) ; also on sheet 18
HSMB_DQ13: U13.B28(HMC_T_DQ_26/DQ3T/DIFFIO_TX_T24p) ; also on sheet 18
HSMB_DQ14: U13.D26(HMC_T_DQ_27/DQ3T/DIFFIO_TX_T22n) ; also on sheet 18
HSMB_DQ15: U13.F22(HMC_T_DQ_28/DQ3T/DIFFIO_RX_T19n) ; also on sheet 18
HSMB_DQ16: U13.F27(HMC_T_DM_4/DQ2T/DIFFIO_TX_T10p) ; also on sheet 18
HSMB_DQ17: U13.G23(HMC_T_DQ_32/DQ2T/DIFFIO_RX_T15n) ; also on sheet 18
HSMB_DQ18: U13.H23(HMC_T_DQ_33/DQ2T/DIFFIO_RX_T15p) ; also on sheet 18
HSMB_DQ19: U13.B31(HMC_T_DQ_34/DQ2T/DIFFIO_TX_T16p) ; also on sheet 18
HSMB_DQ20: U13.E28(HMC_T_DQ_35/DQ2T/DIFFIO_TX_T14n) ; also on sheet 18
HSMB_DQ21: U13.D29(HMC_T_DQ_36/DQ2T/DIFFIO_RX_T11n) ; also on sheet 18
HSMB_DQ22: U13.D30(HMC_T_DQ_37/DQ2T/DIFFIO_RX_T11p) ; also on sheet 18
HSMB_DQ23: U13.C32(HMC_T_DQ_38/DQ2T/DIFFIO_TX_T12p) ; also on sheet 18
HSMB_DQ24: U13.H26(DQ1T/DIFFIO_TX_T2n) ; also on sheet 18
HSMB_DQ25: U13.G25(DQ1T/DIFFIO_RX_T3p) ; also on sheet 18
HSMB_DQ26: U13.G28(DQ1T/DIFFIO_TX_T4p) ; also on sheet 18
HSMB_DQ27: U13.F25(DQ1T/DIFFIO_RX_T3n) ; also on sheet 18
HSMB_DQ28: U13.G29(DQ1T/DIFFIO_TX_T4n) ; also on sheet 18
HSMB_DQ29: U13.H24(DQ1T/DIFFIO_RX_T7n) ; also on sheet 18
HSMB_DQ30: U13.G24(DQ1T/DIFFIO_RX_T7p) ; also on sheet 18
HSMB_DQ31: U13.F30(DQ1T/DIFFIO_TX_T8p) ; also on sheet 18
HSMB_DQS_N0: U13.M21(HMC_T_DQSn_2/DQSn4T/DIFFIO_RX_T29n) ; also on sheet 18
HSMB_DQS_N1: U13.N23(HMC_T_DQSn_3/DQSn3T/DIFFIO_RX_T21n) ; also on sheet 18
HSMB_DQS_N2: U13.K23(HMC_T_DQSn_4/DQSn2T/DIFFIO_RX_T13n) ; also on sheet 18
HSMB_DQS_N3: U13.N24(DQSn1T/DIFFIO_RX_T5n) ; also on sheet 18
HSMB_DQS_P0: U13.N22(HMC_T_DQS_2/DQS4T/DIFFIO_RX_T29p) ; also on sheet 18
HSMB_DQS_P1: U13.M23(HMC_T_DQS_3/DQS3T/DIFFIO_RX_T21p) ; also on sheet 18
HSMB_DQS_P2: U13.L23(HMC_T_DQS_4/DQS2T/DIFFIO_RX_T13p) ; also on sheet 18
HSMB_DQS_P3: U13.M24(DQS1T/DIFFIO_RX_T5p) ; also on sheet 18
HSMB_JTAG_EN: R72.1 SW3.6(B3) ; also on sheet 11
HSMB_PRSNTn: U13.M20(HMC_T_DQS_1/DQS5T/DIFFIO_RX_T37p) ; also on sheet 15 18 20
HSMB_RASn: U13.A23(HMC_T_DQ_6/DQ6T/DIFFIO_TX_T44p) ; also on sheet 18
HSMB_RX_LED: U13.B30(HMC_GND/DIFFIO_TX_T16n) ; also on sheet 20
HSMB_RX_N0: U13.N1(GXB_RX_L8n,GXB_REFCLK_L8n) ; also on sheet 18
HSMB_RX_N1: U13.L1(GXB_RX_L9n,GXB_REFCLK_L9n) ; also on sheet 18
HSMB_RX_N2: U13.J1(GXB_RX_L10n,GXB_REFCLK_L10n) ; also on sheet 18
HSMB_RX_N3: U13.G1(GXB_RX_L11n,GXB_REFCLK_L11n) ; also on sheet 18
HSMB_RX_P0: U13.N2(GXB_RX_L8p,GXB_REFCLK_L8p) ; also on sheet 18
HSMB_RX_P1: U13.L2(GXB_RX_L9p,GXB_REFCLK_L9p) ; also on sheet 18
HSMB_RX_P2: U13.J2(GXB_RX_L10p,GXB_REFCLK_L10p) ; also on sheet 18
HSMB_RX_P3: U13.G2(GXB_RX_L11p,GXB_REFCLK_L11p) ; also on sheet 18
HSMB_SCL: U13.E27(HMC_GND/DIFFIO_TX_T22p) ; also on sheet 18
HSMB_SDA: U13.L20(HMC_GND/DIFFIO_RX_T25n) ; also on sheet 18
HSMB_TX_LED: U13.C24(HMC_GND/DIFFIO_TX_T32n) ; also on sheet 20
HSMB_TX_N0: U13.M3(GXB_TX_L8n) ; also on sheet 18
HSMB_TX_N1: U13.K3(GXB_TX_L9n) ; also on sheet 18
HSMB_TX_N2: U13.H3(GXB_TX_L10n) ; also on sheet 18
HSMB_TX_N3: U13.F3(GXB_TX_L11n) ; also on sheet 18
HSMB_TX_P0: U13.M4(GXB_TX_L8p) ; also on sheet 18
HSMB_TX_P1: U13.K4(GXB_TX_L9p) ; also on sheet 18
HSMB_TX_P2: U13.H4(GXB_TX_L10p) ; also on sheet 18
HSMB_TX_P3: U13.F4(GXB_TX_L11p) ; also on sheet 18
HSMB_WEn: U13.B24(HMC_T_DQ_7/DQ6T/DIFFIO_TX_T42n) ; also on sheet 18
MAX_CSn: U13.M28(DQ10R/DIFFIO_RX_R79n) ; also on sheet 15
MAX_OEn: U13.AC32(DQ4R/DIFFIO_RX_R31n) ; also on sheet 15
MAX_WEn: U13.AD31(DIFFIO_TX_R38p) ; also on sheet 15
PCIE_LED_X1: U13.AK19(HMC_B_ODT_1/DQ7B/DIFFIO_TX_B53n) ; also on sheet 20
PCIE_LED_X4: U13.AD22(DQSn12B/DIFFIO_RX_B91n) ; also on sheet 20
PCIE_PERSTn: J16.A11(PERST_N) ; also on sheet 10
PCIE_PRSNT1n: J16.A1(PRSNT1_N) SW3.1(A1) SW3.2(A2)
PCIE_PRSNT2n_x1: J16.B17(PRSNT2_N_X1) SW3.8(B1)
PCIE_PRSNT2n_x4: J16.B31(PRSNT2_N_X4) SW3.7(B2)
PCIE_REFCLK_N: J16.A14(REFCLK-) U13.V10(REFCLK1Ln)
PCIE_REFCLK_P: J16.A13(REFCLK+) U13.W11(REFCLK1Lp)
PCIE_RX_N0: J16.B15(PET0N) U13.AJ1(GXB_RX_L0n,GXB_REFCLK_L0n)
PCIE_RX_N1: J16.B20(PET1N) U13.AG1(GXB_RX_L1n,GXB_REFCLK_L1n)
PCIE_RX_N2: J16.B24(PET2N) U13.AE1(GXB_RX_L2n,GXB_REFCLK_L2n)
PCIE_RX_N3: J16.B28(PET3N) U13.AC1(GXB_RX_L3n,GXB_REFCLK_L3n)
PCIE_RX_P0: J16.B14(PET0P) U13.AJ2(GXB_RX_L0p,GXB_REFCLK_L0p)
PCIE_RX_P1: J16.B19(PET1P) U13.AG2(GXB_RX_L1p,GXB_REFCLK_L1p)
PCIE_RX_P2: J16.B23(PET2P) U13.AE2(GXB_RX_L2p,GXB_REFCLK_L2p)
PCIE_RX_P3: J16.B27(PET3P) U13.AC2(GXB_RX_L3p,GXB_REFCLK_L3p)
PCIE_SMBCLK: J16.B5(SMCLK) U13.AP5(DQ2B/DIFFIO_TX_B13n)
PCIE_SMBDAT: J16.B6(SMDAT) U13.AJ12(DQ2B/DIFFIO_RX_B14n)
PCIE_TX_CN0: C555.2 J16.A17(PER0N)
PCIE_TX_CN1: C553.2 J16.A22(PER1N)
PCIE_TX_CN2: C551.2 J16.A26(PER2N)
PCIE_TX_CN3: C549.2 J16.A30(PER3N)
PCIE_TX_CP0: C556.2 J16.A16(PER0P)
PCIE_TX_CP1: C554.2 J16.A21(PER1P)
PCIE_TX_CP2: C552.2 J16.A25(PER2P)
PCIE_TX_CP3: C550.2 J16.A29(PER3P)
PCIE_TX_N0: C555.1 U13.AH3(GXB_TX_L0n)
PCIE_TX_N1: C553.1 U13.AF3(GXB_TX_L1n)
PCIE_TX_N2: C551.1 U13.AD3(GXB_TX_L2n)
PCIE_TX_N3: C549.1 U13.AB3(GXB_TX_L3n)
PCIE_TX_P0: C556.1 U13.AH4(GXB_TX_L0p)
PCIE_TX_P1: C554.1 U13.AF4(GXB_TX_L1p)
PCIE_TX_P2: C552.1 U13.AD4(GXB_TX_L2p)
PCIE_TX_P3: C550.1 U13.AB4(GXB_TX_L3p)
PCIE_WAKEn: R107.1 U13.AP6(DQ2B/DIFFIO_TX_B13p)
PCIE_WAKEn_R: J16.B11(WAKE_N) R107.2
REFCLK_QL1_N: U13.AB10(REFCLK0Ln) ; also on sheet 8
REFCLK_QL1_P: U13.AA11(REFCLK0Lp) ; also on sheet 8
REFCLK_QL2_N: U13.T10(REFCLK2Ln) ; also on sheet 8
REFCLK_QL2_P: U13.U11(REFCLK2Lp) ; also on sheet 8
REFCLK_QL3_N: U13.P10(REFCLK3Ln) ; also on sheet 8
REFCLK_QL3_P: U13.R11(REFCLK3Lp) ; also on sheet 8
RREF_TL: R205.1 U13.E1(RREF_TL)
RZQIN_1_5V: R272.2 U13.AP19(RZQ_0/DIFFIO_TX_B49n)
RZQIN_HSMB_VAR: R195.2 U13.A20(RZQ_2/DIFFIO_TX_T48n)
SDI_A_RX_BYPASS: U13.AM9(DIFFIO_TX_B20p) ; also on sheet 15 16
SDI_A_RX_EN: U13.AN4(DQ2B/DIFFIO_TX_B12n) ; also on sheet 15 16
SDI_A_RX_N: R51.1 ; also on sheet 16
SDI_A_RX_P: R50.1 ; also on sheet 16
SDI_A_TX_EN: U13.AM6(DIFFIO_TX_B9n) ; also on sheet 15 16
SDI_A_TX_N: R46.1 ; also on sheet 16
SDI_A_TX_P: R45.1 ; also on sheet 16
SDI_A_TX_SD_HDn: U13.AN5(DIFFIO_TX_B12p) ; also on sheet 16
SDI_CLK148_DN: U13.P31(DQ9R/DIFFIO_RX_R71n) ; also on sheet 8
SDI_CLK148_UP: U13.N34(DQ8R/DIFFIO_RX_R63n) ; also on sheet 8
USB_ADDR0: U13.AL12(DQ4B/DIFFIO_TX_B32p) ; also on sheet 19
USB_ADDR1: U13.AL13(DQ4B/DIFFIO_TX_B32n) ; also on sheet 19
USB_DATA0: U13.AJ15(DQ4B/DIFFIO_RX_B30p) ; also on sheet 19
USB_DATA1: U13.AN11(DQ4B/DIFFIO_TX_B29p) ; also on sheet 19
USB_DATA2: U13.AK15(DQ4B/DIFFIO_RX_B30n) ; also on sheet 19
USB_DATA3: U13.AP11(DQ4B/DIFFIO_TX_B29n) ; also on sheet 19
USB_DATA4: U13.AP9(DQ4B/DIFFIO_TX_B28n) ; also on sheet 19
USB_DATA5: U13.AL15(DQ4B/DIFFIO_RX_B26p) ; also on sheet 19
USB_DATA6: U13.AL11(DQ4B/DIFFIO_TX_B25p) ; also on sheet 19
USB_DATA7: U13.AM15(DQ4B/DIFFIO_RX_B26n) ; also on sheet 19
USB_EMPTY: U13.AP10(DIFFIO_TX_B28p) ; also on sheet 19
USB_FULL: U13.AM11(DIFFIO_TX_B25n) ; also on sheet 19
USB_OEn: U13.AN14(HMC_B_A_15/DQ5B/DIFFIO_RX_B34n) ; also on sheet 19
USB_SCL: U13.AD16(DIFFIO_RX_B31n) ; also on sheet 19
USB_SDA: U13.AC16(DIFFIO_RX_B31p) ; also on sheet 19
USB_WRn: U13.AG15(DQSn4B/DIFFIO_RX_B27n) ; also on sheet 19
USER_DIPSW0: U13.H12(DQ12T/DIFFIO_RX_T95p) ; also on sheet 20
USER_DIPSW1: U13.A2(DIFFIO_TX_T86p) ; also on sheet 20
USER_DIPSW2: U13.E10(DQ12T/DIFFIO_TX_T90n) ; also on sheet 20
USER_DIPSW3: U13.D9(DQ12T/DIFFIO_TX_T92n) ; also on sheet 20
USER_DIPSW4: U13.E9(DQ12T/DIFFIO_TX_T92p) ; also on sheet 20
USER_DIPSW5: U13.D7(DQ12T/DIFFIO_TX_T94n) ; also on sheet 20
USER_DIPSW6: U13.E8(DIFFIO_TX_T96n) ; also on sheet 20
USER_DIPSW7: U13.E7(DIFFIO_TX_T94p) ; also on sheet 20
USER_LED0: U13.AM23(HMC_B_CKE_1/DIFFIO_TX_B60p) ; also on sheet 20
USER_LED1: U13.AE25(DIFFIO_RX_B95n) ; also on sheet 20
USER_LED2: U13.AK29(DIFFIO_TX_B89n) ; also on sheet 20
USER_LED3: U13.AL31(DIFFIO_TX_B92p) ; also on sheet 20
USER_LED4: U13.AF25(DIFFIO_RX_B95p) ; also on sheet 20
USER_LED5: U13.AJ27(DQ12B/DIFFIO_TX_B96n) ; also on sheet 20
USER_LED6: U13.AC22(DQS12B/DIFFIO_RX_B91p) ; also on sheet 20
USER_LED7: U13.AH27(DQ12B/DIFFIO_TX_B96p) ; also on sheet 20
USER_PB0: U13.AK13(DQ3B/DIFFIO_TX_B24p) ; also on sheet 20
USER_PB1: U13.AA15(DIFFIO_RX_B23p) ; also on sheet 20
USER_PB2: U13.AN8(DIFFIO_TX_B17n) ; also on sheet 20
XCVR_RX_N3: R48.2 R51.2 U13.R1(GXB_RX_L7n,GXB_REFCLK_L7n)
XCVR_RX_P3: R47.2 R50.2 U13.R2(GXB_RX_L7p,GXB_REFCLK_L7p)
XCVR_TX_N3: R42.2 R46.2 U13.P3(GXB_TX_L7n)
XCVR_TX_P3: R41.2 R45.2 U13.P4(GXB_TX_L7p)
N124804616: J16.A6(JTAG_TDI) J16.A7(JTAG_TDO)

Not connected (* = marked no-connect by the designer): J16 A5(JTAG_TCK) A8(JTAG_TMS) A19(RSVD2)* A32(RSVD4)* B9(JTAG_TRSTN)* B12(RSVD1)* B30(RSVD3)*; U13 A25(HMC_GND/DIFFIO_TX_T40n)* AD14(DIFFIO_RX_B15p)* AE14(DIFFIO_RX_B15n)* AN7(DQ2B/DIFFIO_TX_B16p)* B29(HMC_GND/DIFFIO_TX_T24n)* E25(HMC_T_DQ_31/DQ3T/DIFFIO_TX_T18n)* E30(DIFFIO_TX_T8n)* F8(DQ12T/DIFFIO_TX_T96p)* F28(HMC_T_DQ_39/DQ2T/DIFFIO_TX_T10n)* L21(HMC_GND/DIFFIO_RX_T25p)* V31(DQ5R/DIFFIO_RX_R39n)*

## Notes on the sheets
sheet 1
- NOTES:
- REV
- DATE
- PAGES
- DESCRIPTION
- 1.
- Project Drawing Numbers:
       Raw PCB
       MMID
       TA
       PBA
       PB
- A
- 29/09/2023
- All
- Released Rev A
- 100-0330705-A1
  99C5L7
  M88458-001
  M88456-001
  M88405-001
- Cyclone V GT Development Kit Board (Non-ENP)
- PAGE
- DESCRIPTION
- PAGE
- DESCRIPTION
- 1
- Title, Notes, Block Diagram, Rev. History
- 30
- Decoupling
- 2
- FPGA Package Top
- 3
- PCI Express Edge Connector
- 4
- Cyclone V GT Banks 3 and 4
- 5
- Cyclone V GT Banks 5 and 6
- 6
- Cyclone V GT Banks 7 and 8
- 7
- Cyclone V GT Transceiver Banks
- 8
- Clocks
- 9
- Cyclone V GT Clocks
- 10
- Cyclone V GT Configuration
- 11
- JTAG
- 12
- DDR3A x40 Hard Memory Controller
- 13
- DDR3A x64 Soft Memory Controller
- 14
- Flash
- 15
- 5M2210 System Controller
- 16
- SDI Port A TX/RX Cable Driver & SMB
- 17
- Ethernet PHY & RJ-45
- 18
- HSMC Port A & Port B
- 19
- On-Board USB Blaster II
- 20
- User I/O
- 21
- ASSP CPLD
- 22
- Cyclone V GT Power
- 23
- Power 1 - DC Input, 12V, 3.3V
- 24
- Power 2 - 1.1V (C5_VCC)
- 25
- Power 3 - 1.2V (C5_GXB)
- 26
- Power 4 - 2.5V (C5_2.5V)
- 27
- Power 5 - 1.5V
- 28
- Power 6 - LTC3605 VAR
- 29
- Power 7 - Power Monitor
- NOTE: THIS DESIGN IS LEVERAGED FROM OLD DESIGN i.e. MMID:979995
sheet 2
- Package Top View
- BANK 8A
- BANK 7A
- VCCIO = 2.5V
- VCCIO = Variable (Default = 2.5V)
- HSMC Port A - LVDS
- HSMC Port B - x32 DQ/DQS
- XCVR BANKS QL2, QL3
- HSMC Port A x2
  HSMC Port B x4
  Hardware Option
   SDI x1
- BANK 5B / 6A
- VCCIO = 1.5V
- DDR3B X64
   (SMC)
- XCVR BANKS QL0, QL1
- PCIe x4
  HSMC Port A x2
- BANK 5A
- VCCIO = 1.8V
- Flash
- BANK 3A
- BANK 3B
- BANK 4A
- VCCIO = 2.5V
- VCCIO = 1.5V
- VCCIO = 1.5V
- Ethernet, PCIe,
  User I/O
- USB Blaster II
  DDR3 x32
   (HMC)
- DDR3 x32
   (HMC)
sheet 3
- PCI Express Edge Connector
- Link Width DIP Switch
- JTAG Chain Control
- ON = not-in-chain
- OFF = in-chain
sheet 4
- Cyclone V GT Banks 3 and 4
- SDI INTERFACE
- VCCIO = 2.5V
- VCCIO = 1.5V
- DDR3A x40 HMC INTERFACE
- VCCIO = 1.5V
- USB INTERFACE
- ETHERNET INTERFACE
- PCIE INTERFACE
- FLASH INTERFACE
- MVE ASSP Core Interface
- USER INTERFACE
- DISPLAY INTERFACE
sheet 5
- Cyclone V GT Banks 5 and 6
- VCCIO = 1.5V
- DDR3B x64 SMC INTERFACE
- VCCIO =1.8V
- FLASH INTERFACE
- VCCIO = 1.5V
- MAX V CONTROL
sheet 6
- Cyclone V GT Banks 7 and 8
- VCCIO = Varies (Default = 2.5V)
- VCCIO = 2.5V
- HSMC PORT A INTERFACE
- HSMC PORT B INTERFACE
- USER I/O INTERFACES
sheet 7
- Cyclone V GT Transceivers and Power
